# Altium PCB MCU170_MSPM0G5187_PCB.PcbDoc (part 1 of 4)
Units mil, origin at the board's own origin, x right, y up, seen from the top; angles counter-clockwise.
Board outline 2300 x 4450 mil, 4 copper layers (Top Layer, VCC Layer, GND Layer, Bottom Layer), stack 62.4 mil thick; 276 components, 190 nets, 913 pads, 323 vias.
Unrouted connection lines stored in the file: 4.
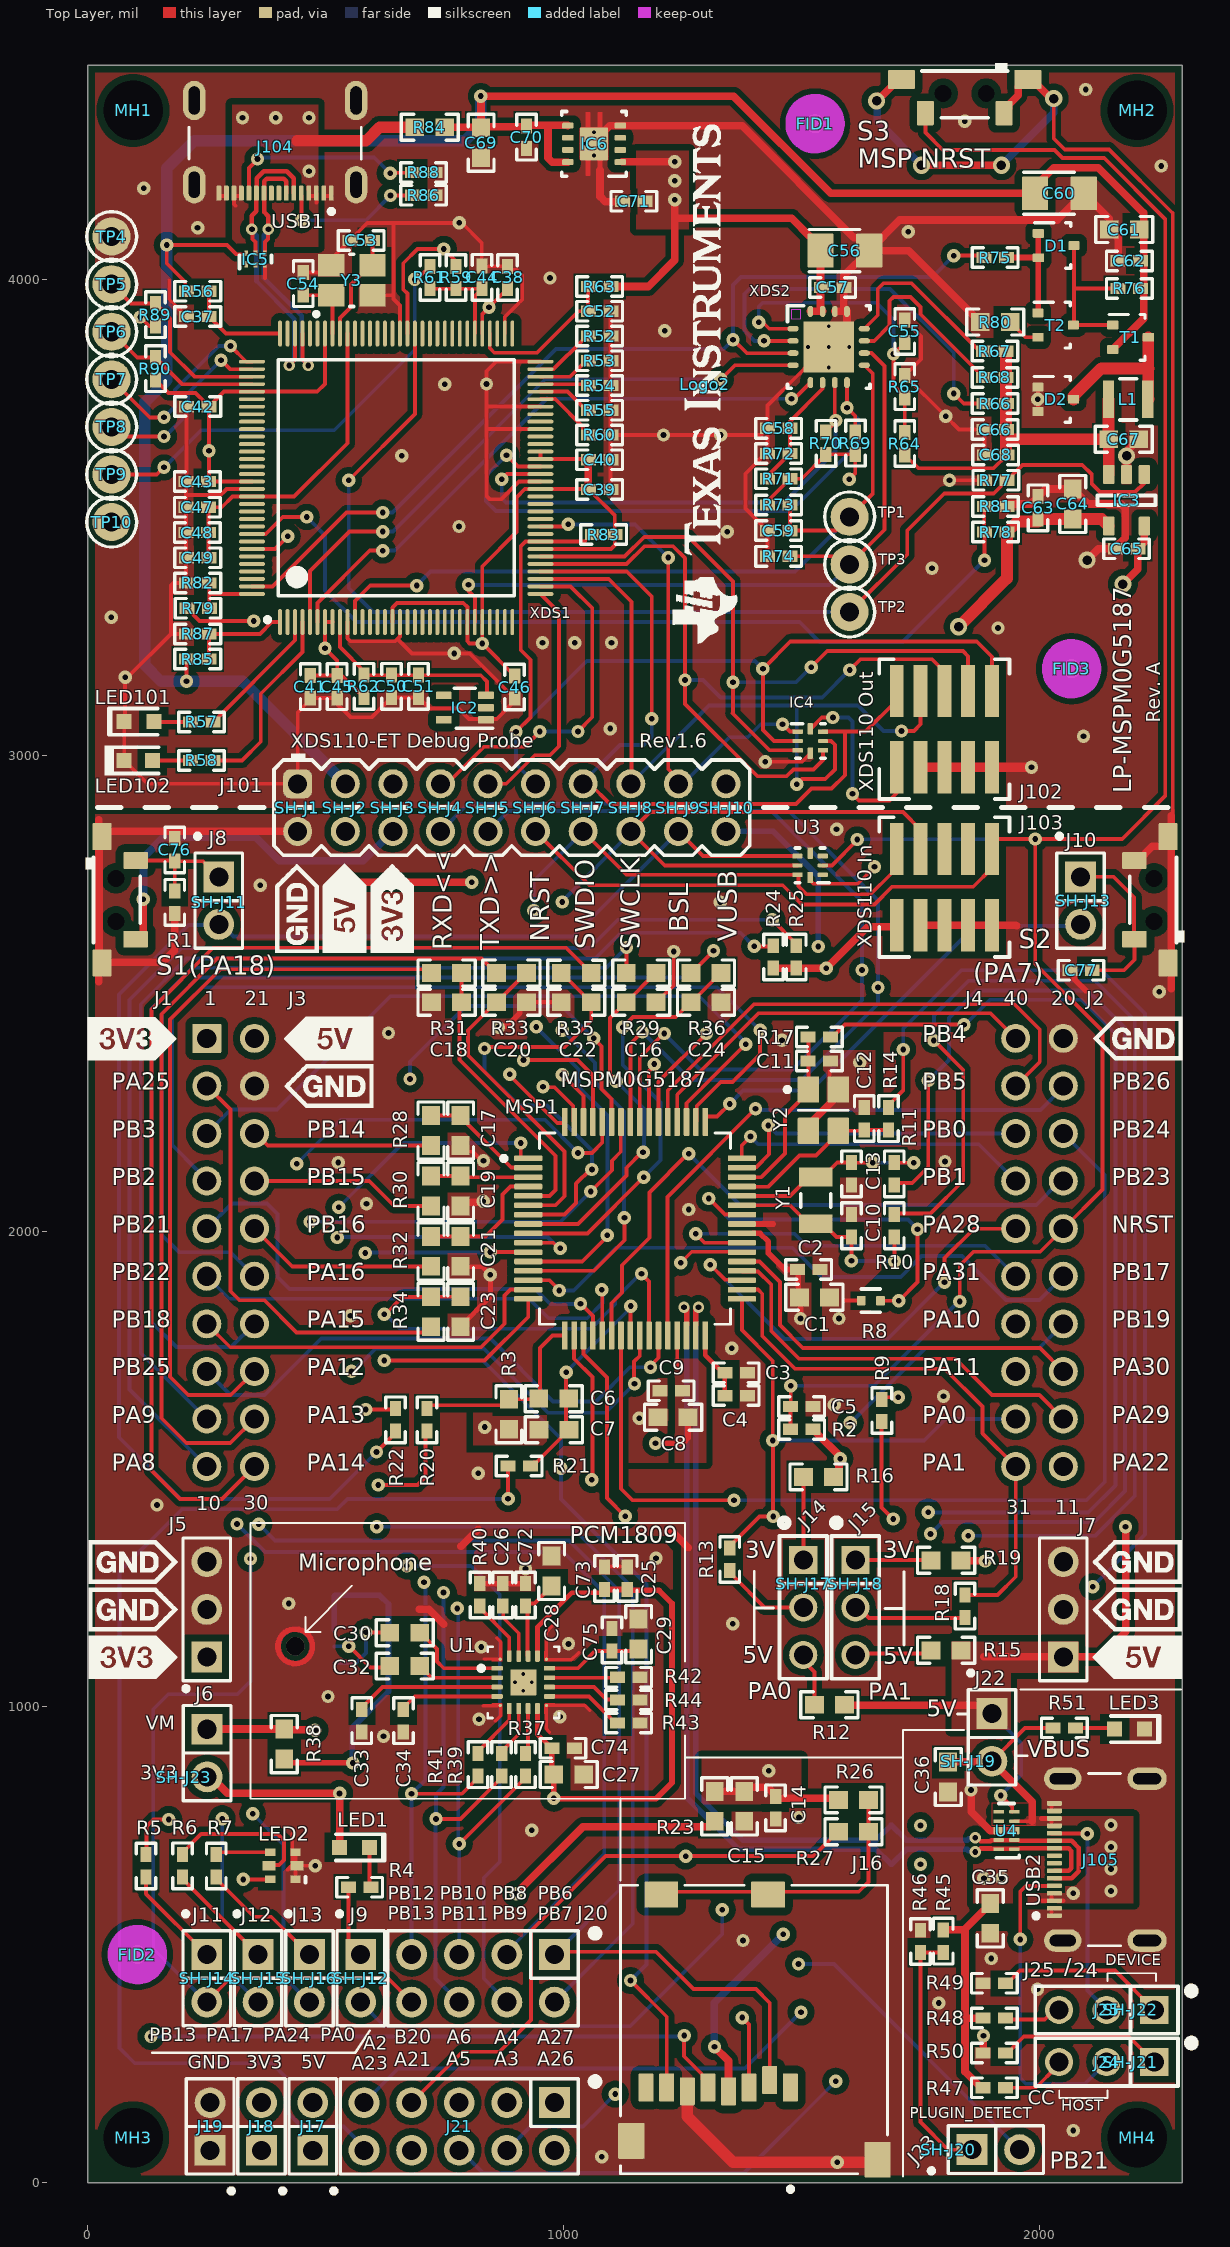
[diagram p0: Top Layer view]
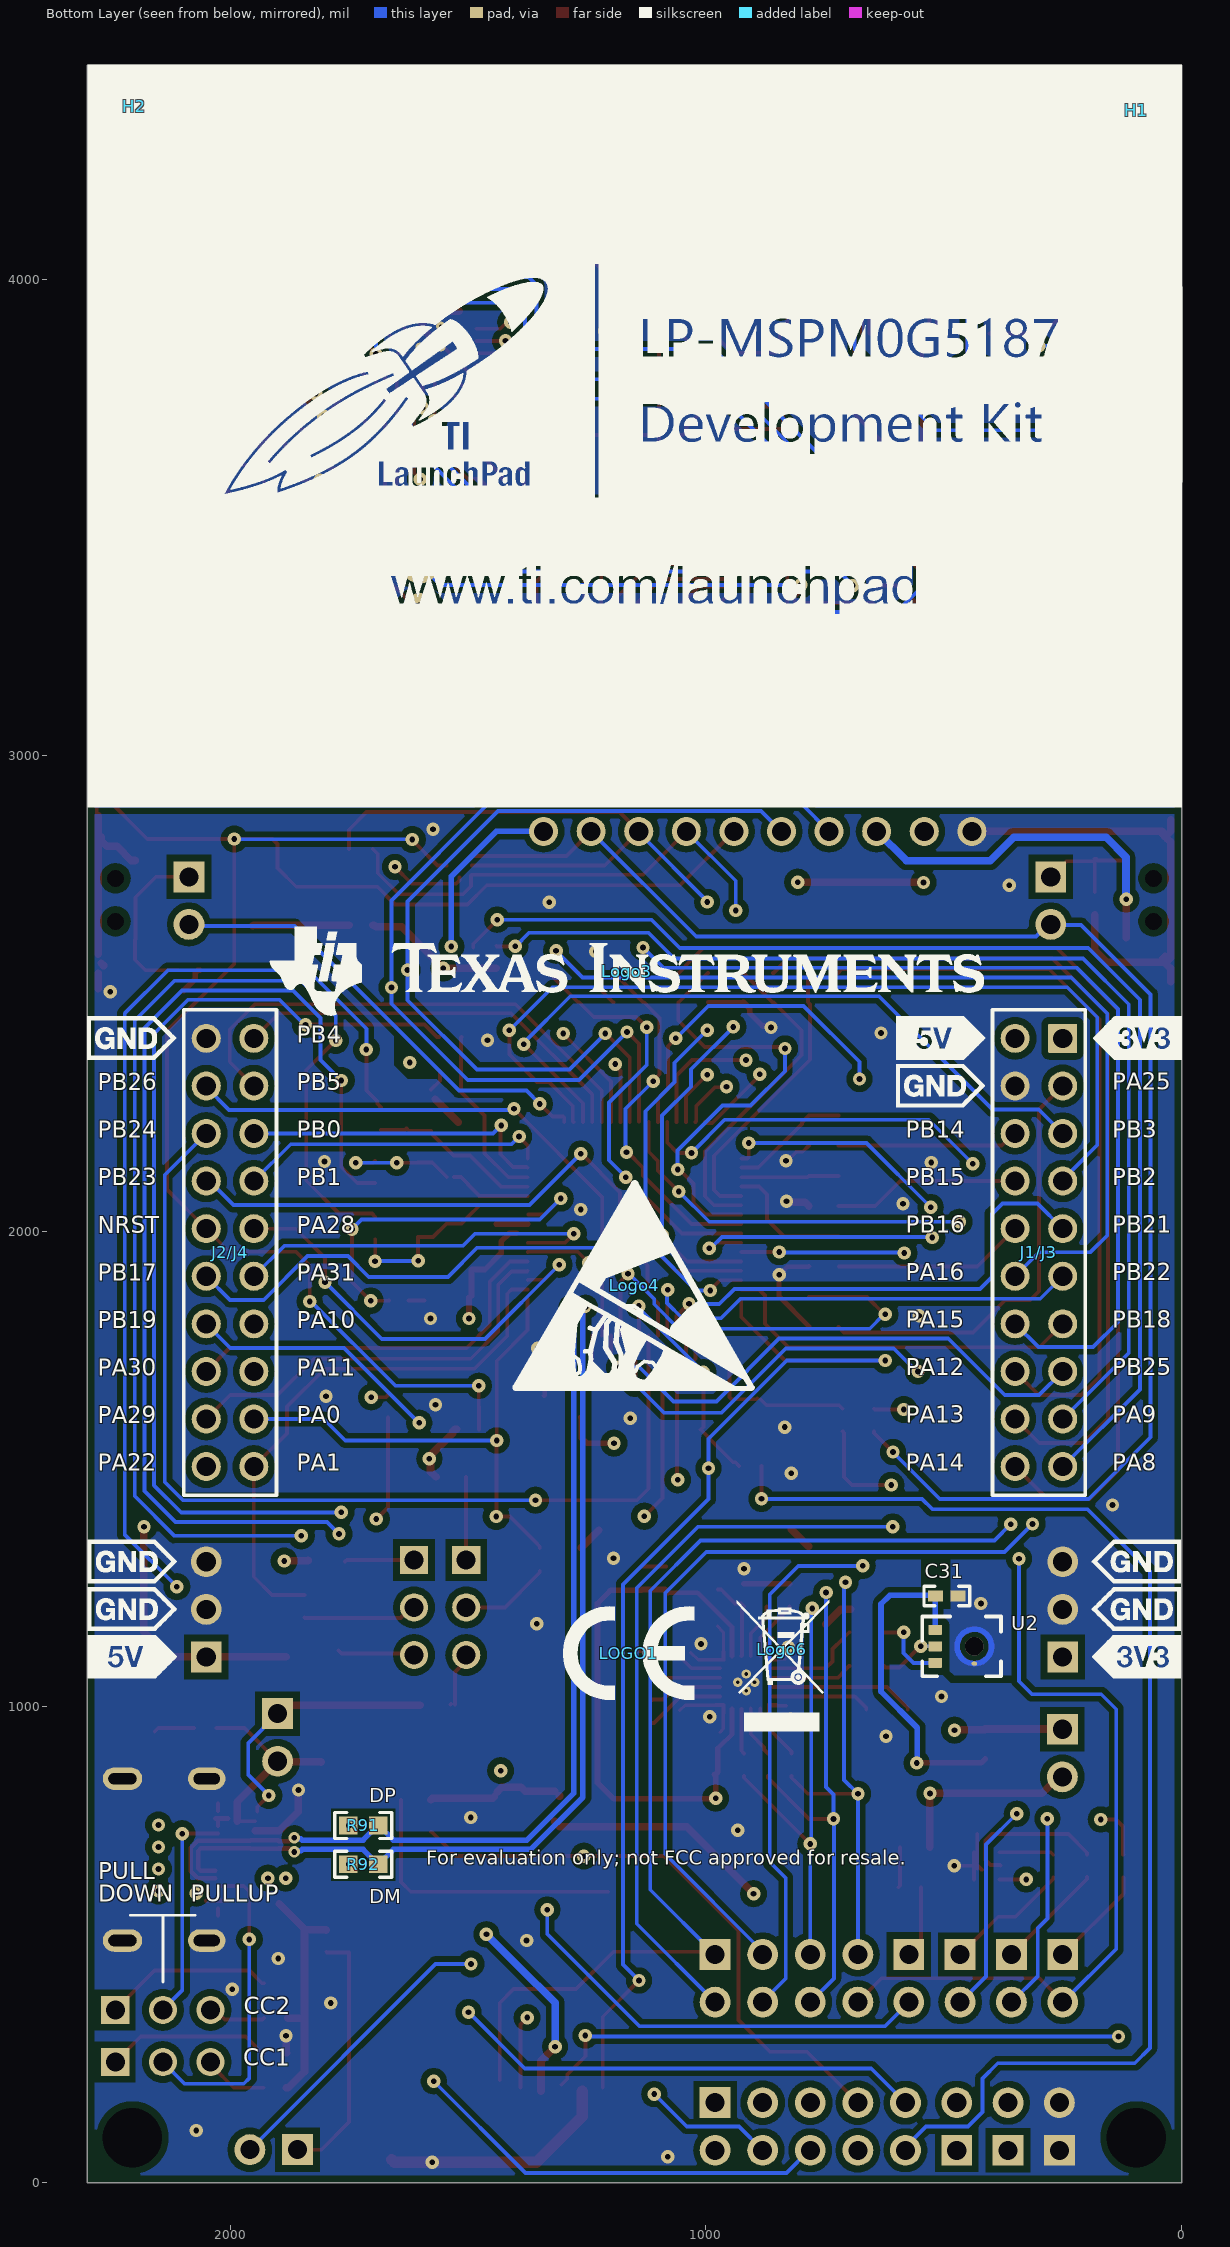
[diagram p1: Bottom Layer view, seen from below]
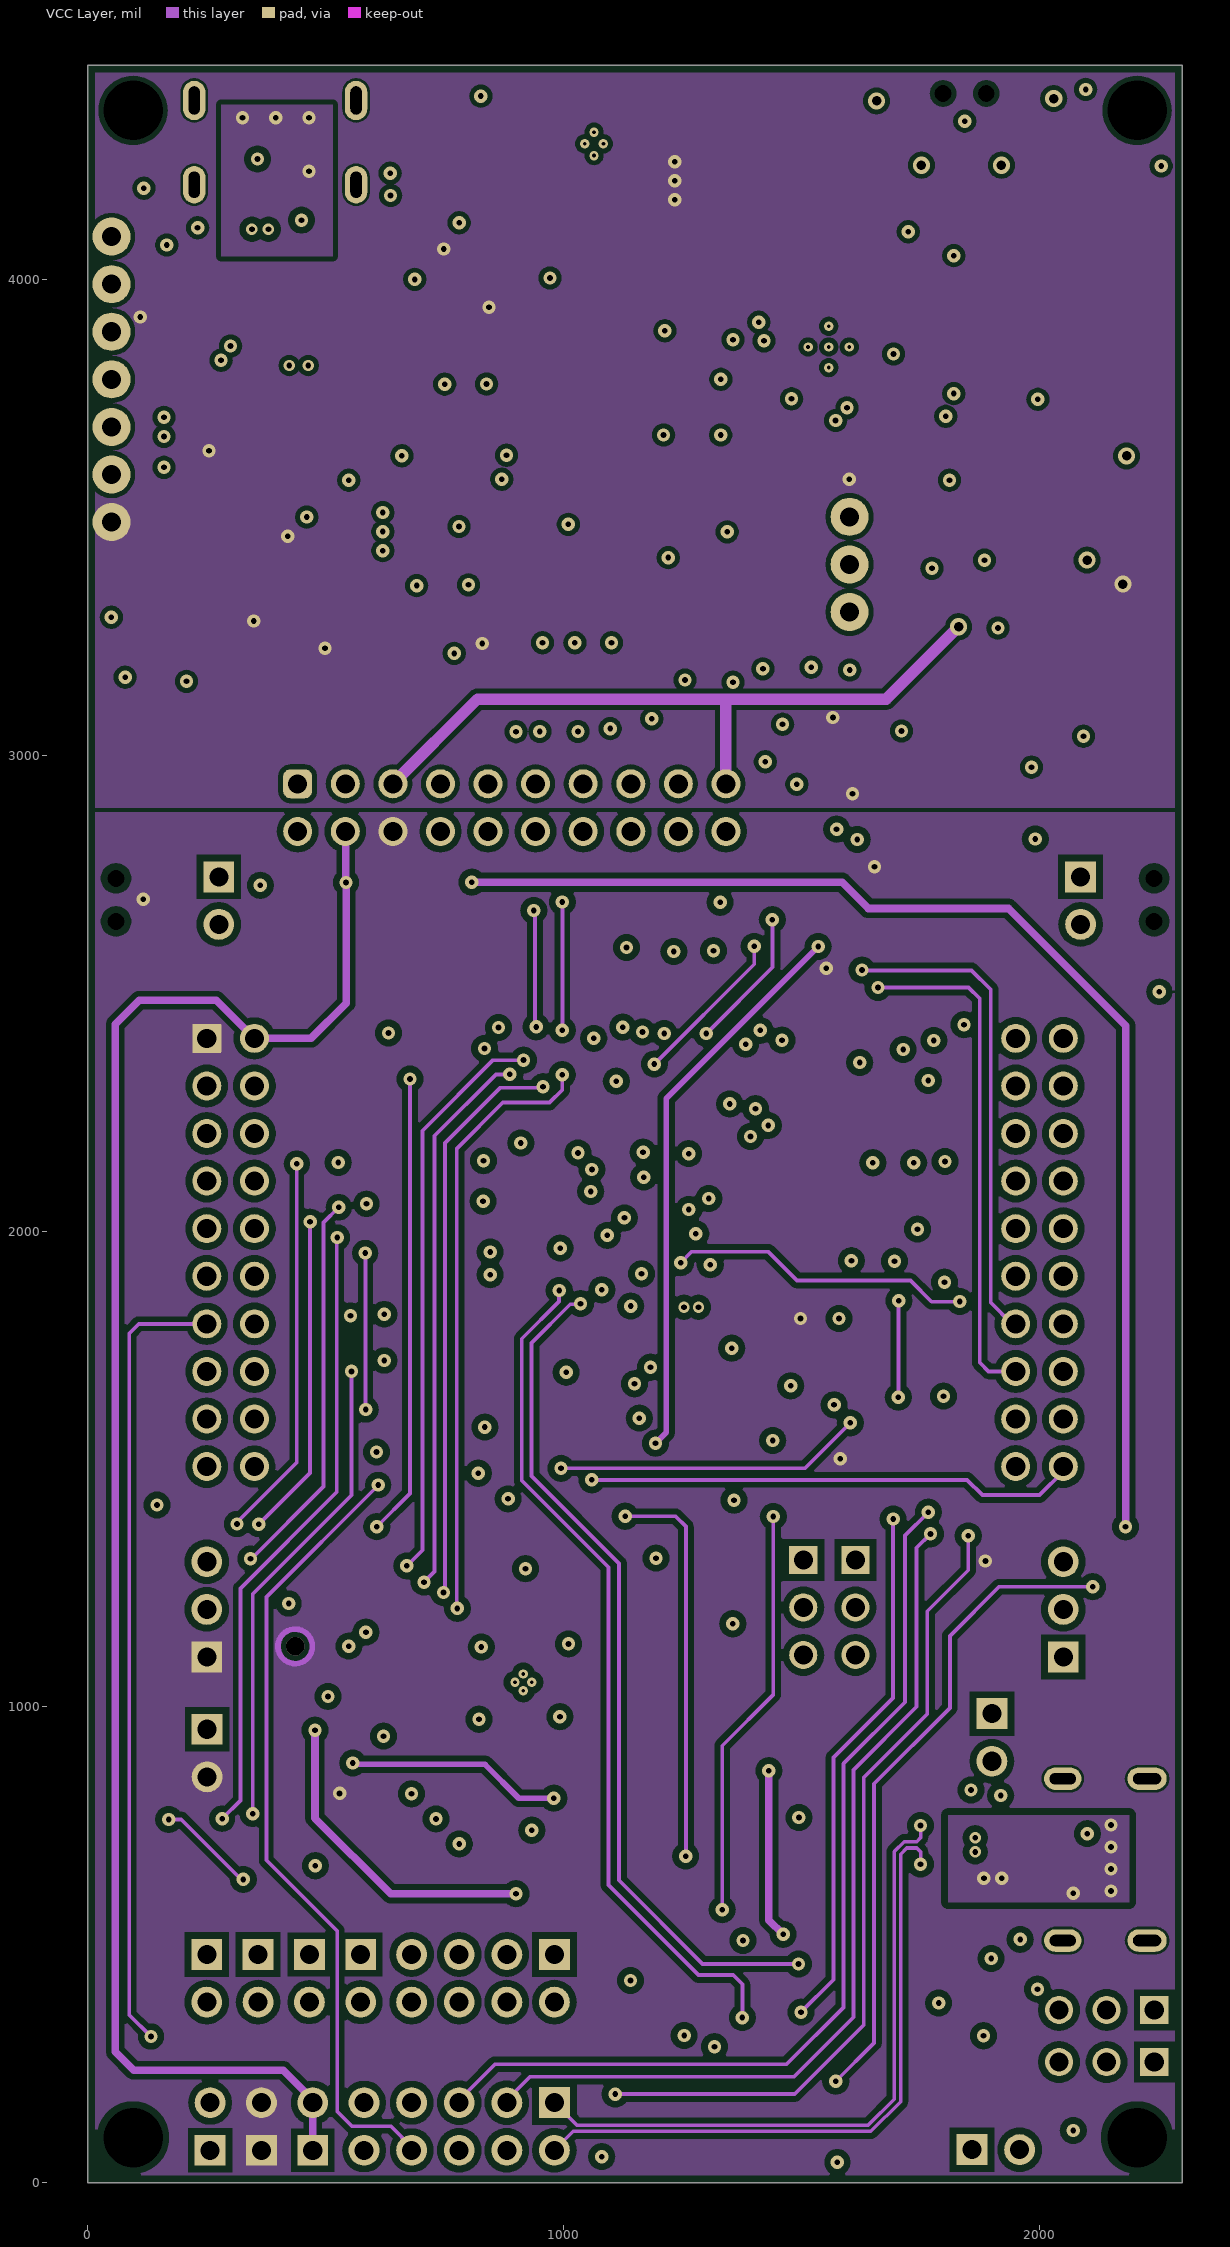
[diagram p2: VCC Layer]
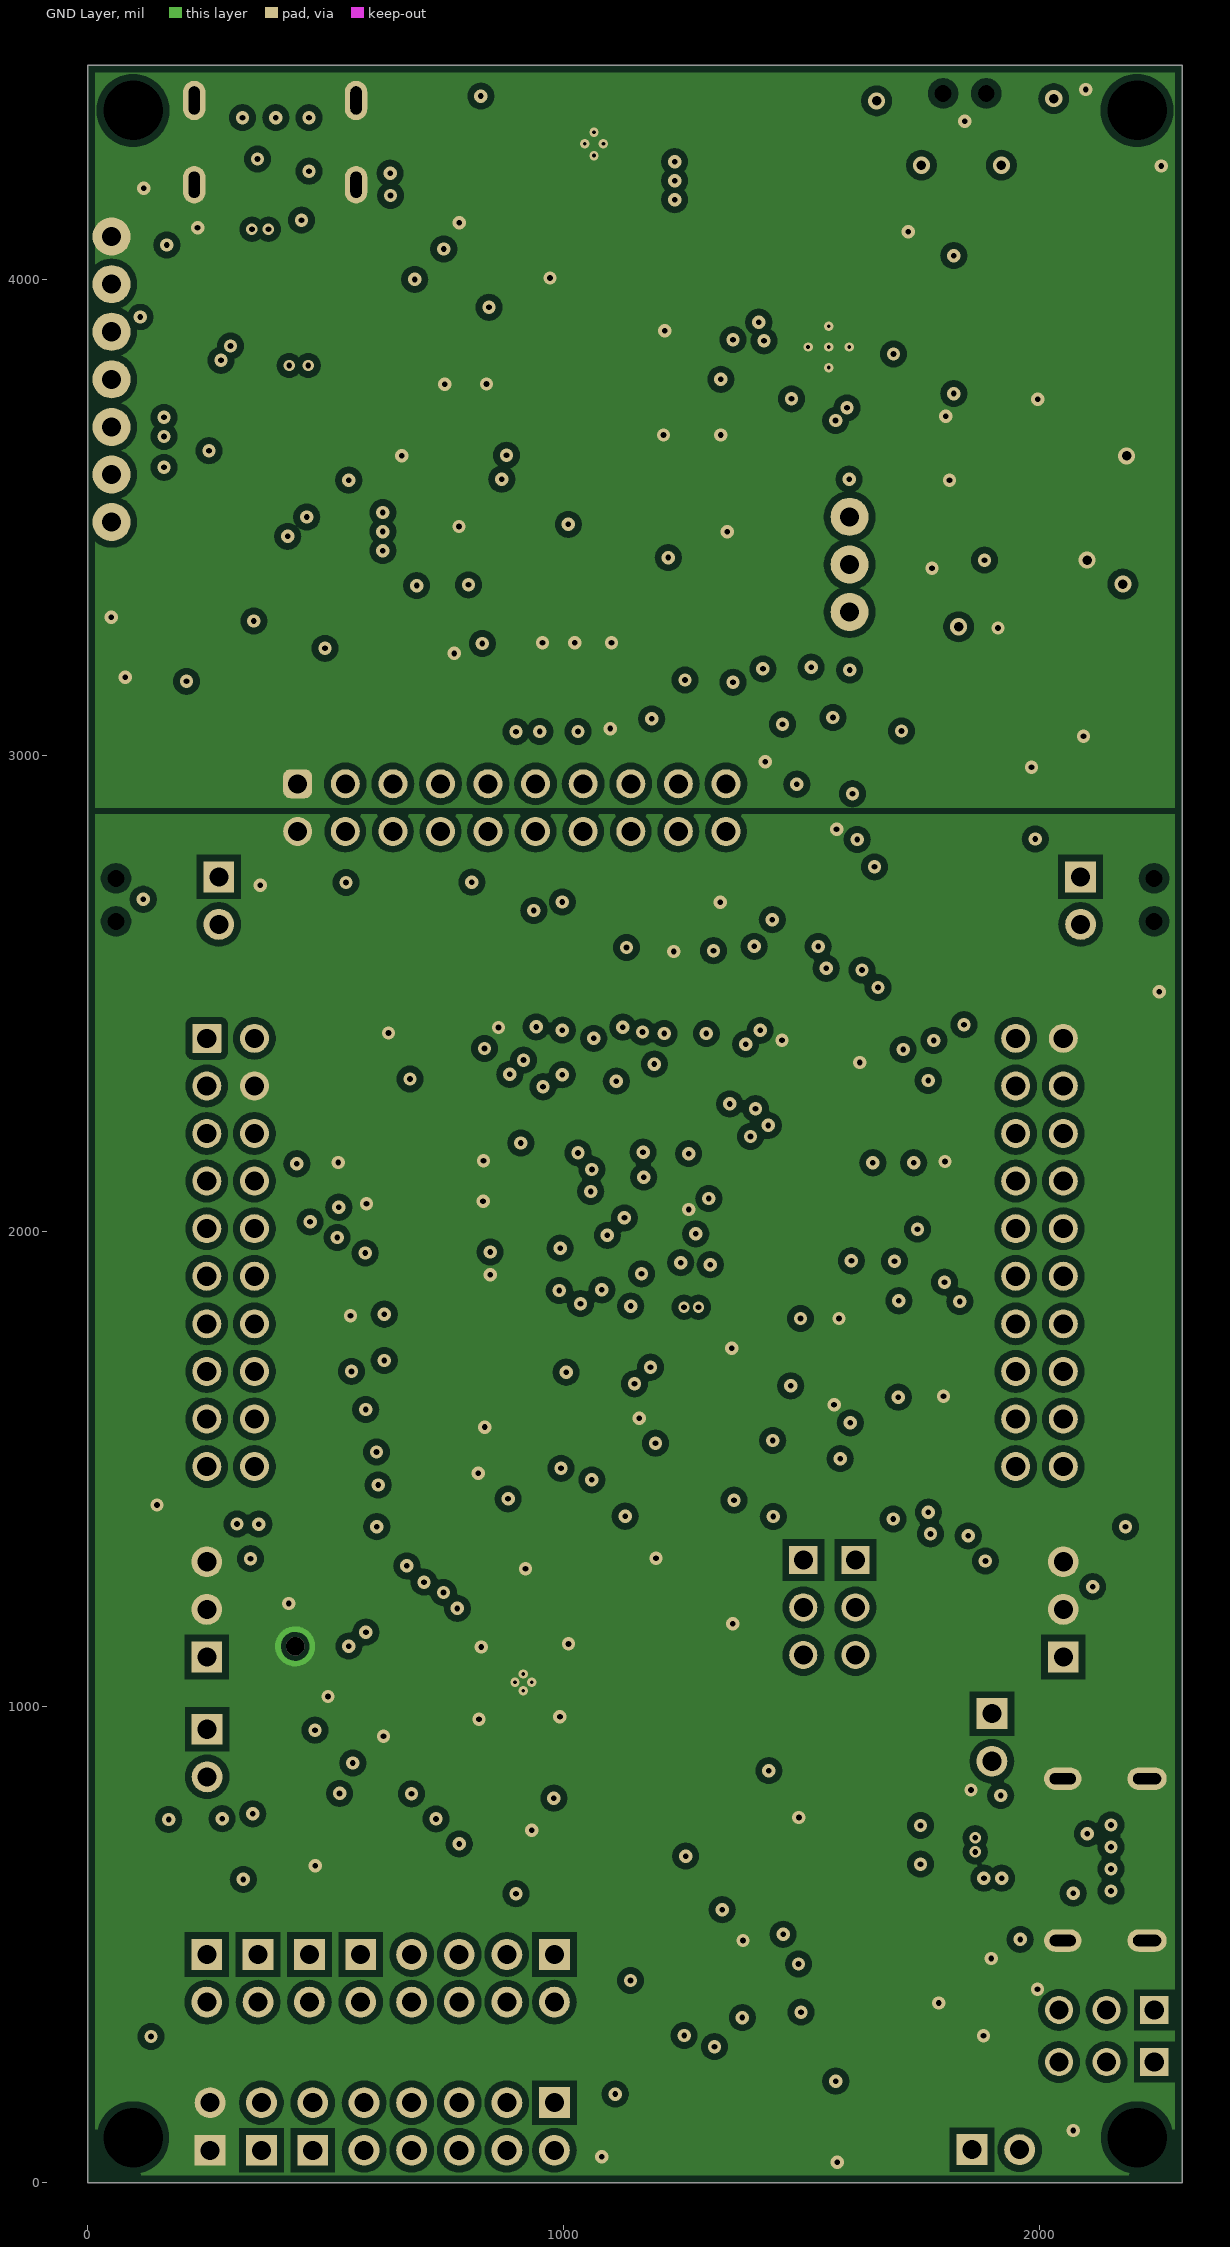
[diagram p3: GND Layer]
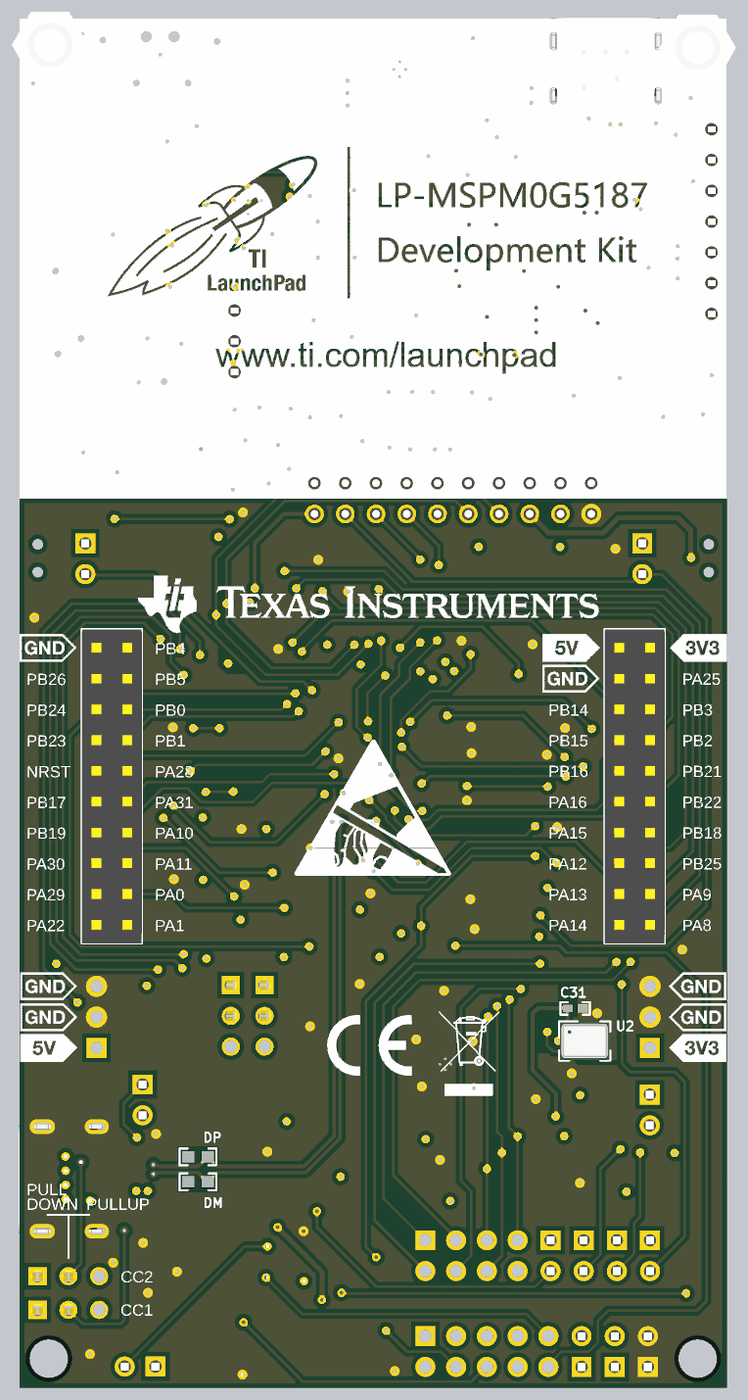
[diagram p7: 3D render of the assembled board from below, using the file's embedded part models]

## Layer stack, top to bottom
Top Solder: solder mask 0.984, SM-004, Dk 4
Top Layer: signal copper 1.4
Dielectric 2: core 8.4, FR-4, Dk 4.2
VCC Layer: signal copper 1.4
Dielectric1: prepreg 40, FR-4, Dk 4.2
GND Layer: signal copper 1.4
Dielectric 3: core 8.4, FR-4, Dk 4.2
Bottom Layer: signal copper 1.4
Bottom Solder: solder mask 0.984, SM-004, Dk 4

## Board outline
0,0 2300,0 2300,4450 0,4450

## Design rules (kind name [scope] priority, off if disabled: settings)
AcuteAngle [All] p1: minimum=4.50000000000000E+0001 checktracksonly=FALSE
AssemblyTestPointUsage [All] p1: valid=2
BoardOutlineClearance BoardOutlineClearance_MountingHoles [OnCopper and InComponentClass('Mounting Holes')] p1: gap=15 ignorepadtopadclearanceinfootprint=FALSE
BoardOutlineClearance BoardOutlineClearance_Poly [OnCopper and IsPoly] p2: gap=15 ignorepadtopadclearanceinfootprint=FALSE
BoardOutlineClearance [OnCopper and Not InComponentClass('Logo') and not InComponentClass('FiducialMark') and not InRegion(1000,500,4000,800) and not InPoly] p3: gap=10 ignorepadtopadclearanceinfootprint=FALSE
Clearance SMD_TYPE_C [((InComponent('J104')) OR (InComponent('J105')))] p1: gap=5 ignorepadtopadclearanceinfootprint=FALSE
Clearance SMD [InNamedPolygon('GND_LAYER_GND_P-001')] p2: gap=10 ignorepadtopadclearanceinfootprint=FALSE except(0: Arc-Hole Track-Hole SMDPad-Hole THPad-Hole Via-Hole Fill-Hole Poly-Hole Region-Hole Text-Hole; 20: SMDPad-SMDPad SMDPad-THPad SMDPad-Via SMDPad-Fill SMDPad-Poly SMDPad-Region SMDPad-Text)
Clearance Clearance_FiducialMark [IsKeepOut and InComponentClass('FiducialMark') vs IsPad and InComponentClass('FiducialMark')] p3: gap=0 ignorepadtopadclearanceinfootprint=FALSE
Clearance Clearance_Keepouts [((IsTrack Or IsArc) And Not InPoly) And IsFree and IsKeepOut vs ((IsTrack Or IsArc) And Not InPoly) And IsFree and IsKeepOut] p4: gap=0 ignorepadtopadclearanceinfootprint=FALSE
Clearance Clearance_Poly [InPolygon] p5: gap=14 ignorepadtopadclearanceinfootprint=FALSE except(0: Arc-Hole Track-Hole SMDPad-Hole THPad-Hole Via-Hole Fill-Hole Poly-Hole Region-Hole Text-Hole; 12: Arc-Fill Arc-Poly Arc-Region Track-Fill Track-Poly Track-Region; 15: THPad-THPad; 16: SMDPad-Fill SMDPad-Poly SMDPad-Region)
Clearance [All] p6: gap=6 ignorepadtopadclearanceinfootprint=FALSE
ComponentClearance ComponentClearance_Standoffs [HasFootprint('KY_MAE-10') vs HasFootprint('NPTH125mil')] p1: gap=0 collisioncheckmode=3 verticalgap=0 showdistances=FALSE
ComponentClearance ComponentClearance_2PinHeaders [HasFootprint('TSW-102-07-G-S') vs HasFootprint('TSW-102-07-G-S')] p2: gap=0 collisioncheckmode=3 verticalgap=0 showdistances=FALSE
ComponentClearance ComponentClearance_TestPoint [HasFootprint('Keystone5001') vs HasFootprint('Keystone5001')] p3: gap=0 collisioncheckmode=3 verticalgap=0 showdistances=FALSE
ComponentClearance ComponentClearance_MountingHoles_FiducialMarks [InComponentClass('Mounting Holes') vs InComponentClass('FiducialMark')] p4: gap=0 collisioncheckmode=3 verticalgap=0 showdistances=FALSE
ComponentClearance ComponentClearance_ShuntToShunt [InComponentClass('Shunt') vs InComponentClass('Shunt')] p5: gap=0 collisioncheckmode=3 verticalgap=0 showdistances=FALSE
ComponentClearance ComponentClearance_Shunt [InComponentClass('Header') vs InComponentClass('Shunt')] p6: gap=0 collisioncheckmode=3 verticalgap=0 showdistances=FALSE
ComponentClearance ComponentClearance_Logo [InComponentClass('Logo')] p7: gap=0 collisioncheckmode=3 verticalgap=0 showdistances=FALSE
ComponentClearance ComponentClearance_ScrewToNut [(HasFootprint('NY PMS 440 0025 PH')) vs (HasFootprint('Keystone_1902C'))] p8: gap=5 collisioncheckmode=3 verticalgap=10 showdistances=FALSE
ComponentClearance ComponentClearance_MountingHoles [InComponentClass('Mounting Holes')] p9: gap=250 collisioncheckmode=3 verticalgap=100000 showdistances=FALSE
ComponentClearance ComponentClearance_SmallPassives [HasFootprint('0201*') or HasFootprint('0402*') or HasFootprint('0508') or HasFootprint('0603*') or HasFootprint('0612') or HasFootprint('0805*') or HasFootprint('0815*') or HasFootprint('0830*') or HasFootprint('1206*') or HasFootprint('1210*') or HasFootprint('1808*') or HasFootprint('1812*') or HasFootprint('1825*') or HasFootprint('2010*') or HasFootprint('2220*') or HasFootprint('2225*') or HasFootprint('2512*') or HasFootprint('2728*') or HasFootprint('3518*') vs HasFootprint('0201*') or HasFootprint('0402*') or HasFootprint('0508') or HasFootprint('0603*') or HasFootprint('0612') or HasFootprint('0805*') or HasFootprint('0815*') or HasFootprint('0830*') or HasFootprint('1206*') or HasFootprint('1210*') or HasFootprint('1808*') or HasFootprint('1812*') or HasFootprint('1825*') or HasFootprint('2010*') or HasFootprint('2220*') or HasFootprint('2225*') or HasFootprint('2512*') or HasFootprint('2728*') or HasFootprint('3518*')] p10: gap=0 collisioncheckmode=3 verticalgap=0 showdistances=FALSE
ComponentClearance ComponentClearance_THtoSMT [IsThruComponent vs IsSMTComponent] p11: gap=0 collisioncheckmode=3 verticalgap=0 showdistances=FALSE
ComponentClearance ComponentClearance_THtoTH [IsThruComponent vs IsThruComponent] p12: gap=0 collisioncheckmode=3 verticalgap=0 showdistances=FALSE
ComponentClearance [All] p13: gap=0 collisioncheckmode=3 verticalgap=0 showdistances=FALSE
DiffPairsRouting DiffPair_MSPDiffPairsRouting [InDifferentialPair ('DifferentialPair_MSP')] p1: maxlimit=16 minlimit=4 mostfreqgap=8 toplayer_prefgap=6 toplayer_minwidth=6 toplayer_maxwidth=12 toplayer_prefwidth=12 midlayer1_prefgap=6 midlayer1_minwidth=6 midlayer1_maxwidth=8 midlayer1_prefwidth=8 midlayer2_prefgap=6 midlayer2_minwidth=6 midlayer2_maxwidth=8 midlayer2_prefwidth=8 bottomlayer_minwidth=6 bottomlayer_maxwidth=12 bottomlayer_prefwidth=12 maxuncoupledlength=100
DiffPairsRouting DiffPair_XDS_USBDiffPairsRouting [InDifferentialPairClass('XDS_USB')] p2: maxlimit=10 minlimit=6 mostfreqgap=8 toplayer_minwidth=6 toplayer_maxwidth=10 toplayer_prefwidth=8 midlayer1_minwidth=6 midlayer1_maxwidth=10 midlayer1_prefwidth=8 midlayer2_minwidth=6 midlayer2_maxwidth=10 midlayer2_prefwidth=8 bottomlayer_minwidth=6 bottomlayer_maxwidth=10 bottomlayer_prefwidth=8 maxuncoupledlength=500
DiffPairsRouting [All] p3: maxlimit=100 minlimit=6 mostfreqgap=10 toplayer_minwidth=6 toplayer_maxwidth=16 toplayer_prefwidth=10 midlayer1_minwidth=6 midlayer1_maxwidth=16 midlayer1_prefwidth=10 midlayer2_minwidth=6 midlayer2_maxwidth=16 midlayer2_prefwidth=10 bottomlayer_minwidth=6 bottomlayer_maxwidth=16 bottomlayer_prefwidth=10 maxuncoupledlength=1000
FabricationTestPointUsage TestPointUsage [All] p1: valid=2 allowmultiple=FALSE
FabricationTestpoint Testpoint [All] p1: side=3 testpointundercomponent=TRUE minsize=40 maxsize=100 preferedsize=60 minholesize=0 maxholesize=40 preferedholesize=32 testpointgrid=1 allowsidetop=TRUE allowsidebottom=TRUE usegrid=TRUE gridtolerance=0.01
FanoutControl Fanout_LCC [IsLCC] p1: bgadir=Out bgaviamode=Centered fanoutstyle=Auto fanoutdirection=Alternating viagrid=1 // Fanout_LCC (Default Rule)
FanoutControl Fanout_BGA [IsBGA] p2: bgadir=Out bgaviamode=Centered fanoutstyle=Auto fanoutdirection=Alternating viagrid=1 // Fanout_BGA (Default Rule)
FanoutControl Fanout_Default [All] p4: bgadir=Out bgaviamode=Centered fanoutstyle=Auto fanoutdirection=Alternating viagrid=1 // Fanout_Default (Default Rule)
FanoutControl Fanout_Small [(CompPinCount < 5)] p5: bgadir=Out bgaviamode=Centered fanoutstyle=Auto fanoutdirection=OutThenIn viagrid=1 // Fanout_Small (Default Rule)
HoleSize [All] p1: absolutevalues=TRUE maxlimit=251 minlimit=7.87 maxpercent=80.000 minpercent=20.000
MatchedLengths DiffPair_MSPMatchedLengths [InDifferentialPair ('DifferentialPair_MSP')] p1: tolerance=2 checknetsindiffpair=FALSE checkdiffpairvsdiffpair=TRUE checkxsignals=TRUE checkothers=TRUE
MatchedLengths DiffPair_XDS_USBMatchedLengths [InDifferentialPairClass('XDS_USB')] p2: tolerance=2 checknetsindiffpair=FALSE checkdiffpairvsdiffpair=TRUE checkxsignals=TRUE checkothers=TRUE
MinimumAnnularRing MinimumAnnularRing_ThermalPadVias [IsVia and InAnyComponent] p1: minimumring=5.91
MinimumAnnularRing [All] p2: minimumring=6
MinimumSolderMaskSliver MinimumSolderMaskSliver_XDS [HasFootprint('PDT0128A')] p1: minsoldermaskwidth=3.6
MinimumSolderMaskSliver MinimumSolderMaskSliver_Logo [InComponentClass('Logo') vs InComponentClass('Logo')] p2: minsoldermaskwidth=0.7
MinimumSolderMaskSliver [All] p3: minsoldermaskwidth=3.94
PlaneClearance [All] p1: clearance=10
PlaneConnect [All] p1: planeconnectstyle=Relief reliefexpansion=10 reliefentries=4 reliefconductorwidth=10 reliefairgap=10
PolygonConnect XDS_USB_VCC_Polygon [All vs IsNamedPolygon('TOP_LAYER_XDS_VBUS_P044')] p1: connectstyle=Direct reliefconductorwidth=10 reliefentries=4 polygonreliefangle="90 Angle" airgapwidth=10
PolygonConnect PolygonConnect_General [All] p2: connectstyle=Direct reliefconductorwidth=10 reliefentries=4 polygonreliefangle="90 Angle" airgapwidth=10
RoutingVias ThermalPadVias [IsVia and InAnyComponent] p1: holewidth=7.87 width=19.68 viastyle="Through Hole" minholewidth=7.87 minwidth=19.68 maxholewidth=16 maxwidth=30
RoutingVias [All] p2: holewidth=12 width=28 viastyle="Through Hole" minholewidth=7.87 minwidth=26 maxholewidth=40 maxwidth=65
SilkToBoardRegionClearance [Not ((IsComment or IsDesignator) And (Hide <> 'False')) and not InRegion(1000,500,4000,800)] p1:
SilkToSilkClearance SilkToSilkClearance_Pb-FreeLogo [(HasFootprint('Pb-Free_Overlay_Medium') OR HasFootprint('Pb-Free_Overlay_Small')) vs (HasFootprint('Pb-Free_Overlay_Medium') OR HasFootprint('Pb-Free_Overlay_Small'))] p1: silktosilkclearance=0
SilkToSilkClearance [All] p2: silktosilkclearance=0
SilkToSolderMaskClearance SilkToComponentPadClearance [(IsPad or IsFill or IsRegion) and InAnycomponent] p1: minsilkscreentomaskgap=0 clearancetoexposedcopper=TRUE
SilkToSolderMaskClearance "Silk to Solder Mask Opening" [All] p2: minsilkscreentomaskgap=0 clearancetoexposedcopper=FALSE
SolderMaskExpansion SolderMaskExpansion_via [isvia] p1: expansion=-16 istentingtop=FALSE
SolderMaskExpansion [All] p2: expansion=2 istentingtop=FALSE
Width Width_Signal_16mil [InNetClass('Power_16mil')] p1: maxlimit=24 minlimit=8 preferedwidth=16 minimp=50.000000 maximp=50.000000 favimp=50.000000
Width Width_Signal_8mil [InNetClass('SIgnal_8mil')] p2: maxlimit=16 minlimit=8 preferedwidth=8 minimp=50.000000 maximp=50.000000 favimp=50.000000
Width [All] p3: maxlimit=100 minlimit=6 preferedwidth=10 checkconnectedcopper=TRUE
14 further rules are at their usual default settings.

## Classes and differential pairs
differential pair class Header_USB: Header_USB
differential pair class MSP_USB: DifferentialPair_MSP
differential pair class XDS_USB: DifferentialPair_XDS
component class MCU170_03_MSPM0G5187_Target_Interface: C25 C26 C27 C28 C29 C30 C31 C32 C33 C34 C35 C36 C72 C73 C74 C75 J22 J23 J24 J25 J105 LED3 R37 R38 R39 R40 R41 R42 R43 R44 R45 R46 R47 R48 R49 R50 R51 U1 U2 U4
component class MCU170_08_Hardware: "30N.C. ROUTE" !PCB FID1 FID2 FID3 H1 H2 LOGO1 Logo2 Logo3 Logo4 Logo5 Logo6 MH1 MH2 MH3 MH4 SH-J1 SH-J2 SH-J3 SH-J4 SH-J5 SH-J6 SH-J7 SH-J8 SH-J9 SH-J10 SH-J11 SH-J12 SH-J13 SH-J14 SH-J15 SH-J16 SH-J17 SH-J18 SH-J19 SH-J20 SH-J21 SH-J22 SH-J23 SH-J101A SH-J101B SH-J101C SH-J101D SH-J101E SH-J101F SH-J101G SH-J101H SH-J101I SH-J101J ZZ1 ZZ2 ZZ3 ZZ4
component class MCU170_07_XDS110-ET_USB_Power: "30N.C. ROUTE" C69 C70 C71 IC5 IC6 J104 R84 R85 R86 R87 R88 R89 R90 TP4 TP5 TP6 TP7 TP8 TP9 TP10
component class MCU170_06_XDS110_Target_Interface: "30N.C. ROUTE" IC4 J101 J102 J103 R83 U3
component class MCU170_05_XDS110-ET_EnergyTrace: "30N.C. ROUTE" C55 C56 C57 C58 C59 C60 C61 C62 C63 C64 C65 C66 C67 C68 D1 D2 IC3 L1 R64 R65 R66 R67 R68 R69 R70 R71 R72 R73 R74 R75 R76 R77 R78 R79 R80 R81 R82 T1 T2 XDS2
component class MCU170_04_XDS110_Debug_Probe: "30N.C. ROUTE" C37 C38 C39 C40 C41 C42 C43 C44 C45 C46 C47 C48 C49 C50 C51 C52 C53 C54 IC2 LED101 LED102 R52 R53 R54 R55 R56 R57 R58 R59 R60 R61 R62 R63 TP1 TP2 TP3 XDS1 Y3
component class MCU170_02_BoosterPack_Connectors: "30N.C. ROUTE" C14 C15 C16 C17 C18 C19 C20 C21 C22 C23 C24 J1/J3 J2/J4 J16 J17 J18 J19 J20 J21 R23 R24 R25 R26 R27 R28 R29 R30 R31 R32 R33 R34 R35 R36 R91 R92
component class MCU170_01_MSPM0G5187_Target_Device: "30N.C. ROUTE" C1 C2 C3 C4 C5 C6 C7 C8 C9 C10 C11 C12 C13 C76 C77 J5 J6 J7 J8 J9 J10 J11 J12 J13 J14 J15 LED1 LED2 MSP1 R1 R2 R3 R4 R5 R6 R7 R8 R9 R10 R11 R12 R13 R14 R15 R16 R17 R18 R19 R20 R21 R22 S1 S2 S3 Y1 Y2
component class FiducialMark: "30N.C. ROUTE" FID1 FID2 FID3
component class AssemblyNote: "30N.C. ROUTE" ZZ2 ZZ3 ZZ4 ZZ6
component class Logo: "30N.C. ROUTE" Logo2 Logo3
component class Header: J5 J6 J7 J8 J9 J10 J11 J12 J13 J14 J15 J17 J18 J19 J20 J21 J22 J23 J24 J25 J101
component class Shunt: SH-J1 SH-J2 SH-J3 SH-J4 SH-J5 SH-J6 SH-J7 SH-J8 SH-J9 SH-J10 SH-J11 SH-J12 SH-J13 SH-J14 SH-J15 SH-J16 SH-J17 SH-J18 SH-J19 SH-J20 SH-J21 SH-J22 SH-J23
differential pair Header_USB: +NetJ21_1 -NetJ21_2
differential pair DifferentialPair_MSP: +31_PA27_DP -30_PA26_DM
differential pair DifferentialPair_XDS: +XDS_DP -XDS_DM

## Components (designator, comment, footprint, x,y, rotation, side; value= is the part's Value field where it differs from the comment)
C1 "GRM188R60J106ME84" 0603 1526.99,1860.62 r0 top value=10uF
C2 "GRM155R61H104ME14D" 0402 1515.01,1919.19 r0 top value=0.1uF
C3 "GRM155R60J474KE19D" 0402 1362.36,1702.11 r0 top value=0.47uF
C4 "GRM155R61H104ME14D" 0402 1362.36,1654.1 r0 top value=0.1uF
C5 "GRM155R61C103KA01D" 0402 1500.28,1631.29 r0 top value=0.01uF
C6 "C1608X5R1E105K080AC" 0603 979.1,1647.87 r180 top value=1uF
C7 "C1608X5R1E105K080AC" 0603 979.57,1582.37 r180 top value=1uF
C8 "C1608X5R1E105K080AC" 0603 1230,1608.79 r0 top value=1uF
C9 "GRM155R61H104ME14D" 0402 1226,1664.49 r0 top value=0.1uF
C10 "GRM1555C1H150JA01D" 0402 1605,2011.17 r90 top value=15pF
C11 "GRM1555C1H150JA01D" 0402 1537.36,2357.28 r0 top value=15pF
C12 "GRM1555C1H150JA01D" 0402 1631.61,2236.41 r90 top value=15pF
C13 "GRM1555C1H150JA01D" 0402 1605,2120.31 r270 top value=15pF
C14 "C0402C104K8RACTU" 0402 1445.52,787.84 r90 top value=0.1uF
C15 "EMK107BBJ106MA-T" 0603 1379.42,790.91 r90 top value=10uF
C16 "GCM188R71C104KA37J" 0603 1162.81,2480.8 r180 top value=0.1uF
C17 "GCM188R71C104KA37J" 0603 783.43,2211.25 r90 top value=0.1uF
C18 "GCM188R71C104KA37J" 0603 753.88,2480.87 r0 top value=0.1uF
C19 "GCM188R71C104KA37J" 0603 783.43,2084.27 r90 top value=0.1uF
C20 "GCM188R71C104KA37J" 0603 890.19,2480.87 r180 top value=0.1uF
C21 "GCM188R71C104KA37J" 0603 783.43,1957.3 r90 top value=0.1uF
C22 "GCM188R71C104KA37J" 0603 1026.5,2480.87 r0 top value=0.1uF
C23 "GCM188R71C104KA37J" 0603 783.43,1830.32 r90 top value=0.1uF
C24 "GCM188R71C104KA37J" 0603 1299.12,2480.87 r180 top value=0.1uF
C25 "GRM155R61A105KE15D" 0402 1133.72,1270 r90 top value=1uF
C26 "GRM155R61A105KE15D" 0402 871.91,1235.28 r270 top value=1uF
C27 "C1608X6S1A106M080AC" 0603 1010.7,857.89 r0 top value=10uF
C28 "C1608X6S1A106M080AC" 0603 974.63,1285.63 r270 top value=10uF
C29 "C1608X6S1A106M080AC" 0603 1157.41,1153.04 r270 top value=10uF
C30 "C1608X7R1C105K080AC" 0603 666.16,1156 r180 top value=1uF
C31 "GRM155R61H104ME14D" 0402 493.48,1232.96 r180 bottom value=0.1uF
C32 "C1608X7R1C105K080AC" 0603 666.16,1085.86 r180 top value=1uF
C33 "GRM155R61A105KE15D" 0402 575.73,970.89 r270 top value=1uF
C34 "GRM155R61A105KE15D" 0402 663.11,970.89 r270 top value=1uF
C35 "GRM188R60J106ME84" 0603 1896.49,555.52 r270 top value=10uF
C36 "EMK107BBJ106MA-T" 0603 1807.96,852.71 r270 top value=10uF
C37 "GRM155R70J104KA01D" 0402 231,3922 r180 top value=0.1uF
C38 "GRM155R71E103KA01D" 0402 882,4004 r90 top value=0.01uF
C39 "GRM155R71E103KA01D" 0402 1075.66,3558.44 r0 top value=0.01uF
C40 "GRM155R71E103KA01D" 0402 1075.66,3621 r0 top value=0.01uF
C41 "GRM155R70J104KA01D" 0402 467.5,3144 r270 top value=0.1uF
C42 "GRM155R70J104KA01D" 0402 231,3732.61 r180 top value=0.1uF
C43 "C1005X5R1E105K050BC" 0402 230,3575 r180 top value=1uF
C44 "GRM155R70J104KA01D" 0402 828.45,4004.33 r90 top value=0.1uF
C45 "C1005X5R1E105K050BC" 0402 524,3144 r270 top value=1uF
C46 "GRM155R71E103KA01D" 0402 897,3143.38 r270 top value=0.01uF
C47 "GRM155R60J225KE95D" 0402 230,3521 r180 top value=2.2uF
C48 "GRM155R70J104KA01D" 0402 230,3468 r180 top value=0.1uF
C49 "C1005X5R1E105K050BC" 0402 231,3415 r180 top value=1uF
C50 "GRM155R71E103KA01D" 0402 638,3144.63 r270 top value=0.01uF
C51 "GRM155R70J104KA01D" 0402 695,3144.63 r270 top value=0.1uF
C52 "GRM155R70J104KA01D" 0402 1075.66,3933 r0 top value=0.1uF
C53 "GRM1555C1H120JA01D" 0402 574.38,4081.97 r180 top value=12pF
C54 "GRM1555C1H120JA01D" 0402 452.72,3991 r90 top value=12pF
C55 "GRM1555C1H330JA01D" 0402 1717,3890.62 r90 top value=33pF
C56 "TAJA475K016RNJ" 3216-18 1591.02,4060.58 r0 top value=4.7uF
C57 "GRM155R70J104KA01D" 0402 1565.38,3983 r0 top value=0.1uF
C58 "GRM1555C1H330JA01D" 0402 1452,3687 r180 top value=33pF
C59 "GCM155R71H102KA37D" 0402 1452,3472 r180 top value=1000pF
C60 "TAJA475K016RNJ" 3216-18 2042,4181 r0 top value=4.7uF
C61 "GRM188R61C475KAAJ" 0603 2178,4104.87 r0 top value=4.7uF
C62 "GRM155R70J104KA01D" 0402 2189,4039 r180 top value=0.1uF
C63 "GRM155R70J104KA01D" 0402 1997,3520 r90 top value=0.1uF
C64 "GRM188R60J476ME15D" 0603 2070,3528 r90 top value=47uF
C65 "GRM155R71C224KA12D" 0402 2183,3434 r180 top value=0.22uF
C66 "GRM155R71C224KA12D" 0402 1907,3684.35 r180 top value=0.22uF
C67 "GRM188R61C475KAAJ" 0603 2177,3664 r180 top value=4.7uF
C68 "GRM155R70J104KA01D" 0402 1908,3631 r180 top value=0.1uF
C69 "GRM188R60J106ME84" 0603 826.42,4287.12 r270 top value=10uF
C70 "C1005X5R1E105K050BC" 0402 921.91,4299.1 r270 top value=1uF
C71 "GRM155R60J225KE95D" 0402 1147.66,4164.08 r180 top value=2.2uF
C72 "GRM155R61H104ME14D" 0402 919.92,1235.28 r90 top value=0.1uF
C73 "GRM155R61H104ME14D" 0402 1085.71,1270 r90 top value=0.1uF
C74 "GRM155R61H104ME14D" 0402 998.72,913.16 r0 top value=0.1uF
C75 "GRM155R61H104ME14D" 0402 1101.75,1141.06 r90 top value=0.1uF
C76 "CC0402MRX5R6BB105" 0402 182.65,2800.88 r90 top value=1uF
C77 "CC0402MRX5R6BB105" 0402 2087.24,2548.2 r180 top value=1uF
D1 "BAS40-05W,115" SOT-323 2035,4071.13 r0 top value=40V
D2 "BAS40-05W,115" SOT-323 2034,3748 r0 top value=40V
FID1 "Fiducial" Fiducial10-30 1528.31,4327.4 r0 top
FID2 "Fiducial" Fiducial10-30 104,479.62 r90 top
FID3 "Fiducial" Fiducial10-30 2067.55,3181.73 r90 top
H1 "MAE-10" KY_MAE-10 95,4355 r180 bottom
H2 "MAE-10" KY_MAE-10 2201,4363.78 r180 bottom
IC2 "LM4040C25IDCKR" DCK0005A_N 792.34,3100.16 r180 top
IC3 "TPS2102DBVR" DBV0005A_N 2183,3535.87 r270 top
IC4 "TPD6E004RSER" RSE0008A 1518.56,3029.88 r0 top
IC5 "TPD4E004DRYR" DRY0006A 352.36,4042.78 r90 top
IC6 "TPS73533DRBT" DRB0008A 1063.84,4284.85 r180 top
J1/J3 "SSQ-110-03-T-D" BoosterPack_40pin_J1J3 300,1955 r180 bottom locked
J2/J4 "SSQ-110-03-T-D" BoosterPack_40pin_J2J4 2000,1955 r180 bottom locked
J5 "PEC03SAAN" PEC03SAAN_Launchpad_3V3 250,1205 r90 top locked
J6 "90120-0122" CONN_90120-0122 250.8,903 r270 top
J7 "PEC03SAAN" PEC03SAAN_Launchpad_5V0 2050,1205 r90 top locked
J8 "90120-0122" CONN_90120-0122 275.18,2694.45 r270 top
J9 "90120-0122" CONN_90120-0122 573.53,429.62 r270 top
J10 "90120-0122" CONN_90120-0122 2086.38,2694.45 r270 top
J11 "90120-0122" CONN_90120-0122 250,429.62 r270 top
J12 "90120-0122" CONN_90120-0122 357.84,429.62 r270 top
J13 "90120-0122" CONN_90120-0122 465.68,429.62 r270 top
J14 "PEC03SAAN" CONN_PEC03SAAN 1503.61,1208.99 r270 top
J15 "PEC03SAAN" CONN_PEC03SAAN 1613.12,1208.99 r270 top
J16 "693071010811" FP-693071010811_CONN_SMT_MEMORY-MFG 1400,322 r0 top locked
J17 "90120-0122" CONN_90120-0122 472.69,118.18 r90 top
J18 "90120-0122" CONN_90120-0122 364.85,118.18 r90 top
J19 "90120-0122" CONN_90120-0122 257.01,118.18 r90 top
J20 "PEC04DAAN" CONN_PEC04DAAN 830.54,429.62 r180 top locked
J21 "PEC05DAAN" CONN_PEC05DAAN 780.54,118.18 r180 top locked
J22 "90120-0122" CONN_90120-0122 1900,935.77 r270 top
J23 "90120-0122" CONN_90120-0122 1908.32,69.43 r0 top
J24 "PEC03SAAN" CONN_PEC03SAAN 2141.16,253.58 r180 top
J25 "PEC03SAAN" CONN_PEC03SAAN 2141.16,363.09 r180 top
J101 "PEC10DAAN" SULLINS_PEC10DAAN 891.04,2890 r270 top locked
J102 "FTSH-105-01-L-DV-K" Samtec_FTSH-105-01-x-DV-K 1800,3055 r90 top
J103 "FTSH-105-01-L-DV-K" Samtec_FTSH-105-01-x-DV-K 1800,2723 r90 top
J104 "MUP-U20405" FP-MUP-U20405_USB_CONN-MFG 393.7,4317 r180 top locked
J105 "MUP-U20405" FP-MUP-U20405_USB_CONN-MFG 2167,679 r90 top locked
L1 "CBC2518T2R2M" CBC2518 2186.4,3748 r180 top value=2.2uH
LED1 "BR1111C-TR" 1111C_Red 560.57,704.89 r0 top value=Red
LED2 "19-337/R6GHBHC-A01/2T" 19-337_RGB 410,666 r180 top value=Rgb
LED3 "BR1111C-TR" 1111C_Red 2189.6,953.41 r0 top value=Red
LED101 "BR1111C-TR" 1111C_Red 107.12,3070.41 r180 top value=Red
LED102 "LTST-C190GKT" LED_LTST-C190 106,2989 r180 top value=Green
LOGO1 "CE Mark" CE_Mark_5mm 1162.08,1113 r180 bottom
Logo2 "Texas Instruments" TI_Horizontal_Overlay_Small 1296.33,3779.83 r90 top
Logo3 "Texas Instruments" TI_Horizontal_Overlay_Medium 1166,2546 r180 bottom
Logo4 "ESD Susceptible" ESD_Overlay_Large 1150,1885.69 r180 bottom
Logo5 "FCC disclaimer" FCC_disclaimer 3226,2019 r0 bottom
Logo6 "WEEE logo" WEEE_Minimum 840.07,1120.77 r180 bottom
MH1 "MTG_NoPads" NPTH125mil 95,4355 r0 top locked
MH2 "MTG_NoPads" NPTH125mil 2205,4355 r0 top locked
MH3 "MTG_NoPads" NPTH125mil 95,95 r0 top locked
MH4 "MTG_NoPads" NPTH125mil 2205,95 r0 top locked
MSP1 "MSPM0G5187SPMR" PM0064A-MFG 1150,2005 r0 top locked
R1 "CRCW040247K0JNED" 0402 182.65,2690.69 r90 top value=47k
R2 "CRCW040247K0JNED" 0402 1500.28,1583.28 r0 top value=47k
R3 "RC0603JR-070RL" 0603 884.91,1615.08 r90 top value=0
R4 "CRCW0402470RJNED" 0402 571.33,621.12 r0 top value=470
R5 "CRCW0402220RJNED" 0402 122.5,665.69 r90 top value=220
R6 "CRCW0402330RJNED" 0402 199.17,666 r90 top value=330
R7 "CRCW0402330RJNED" 0402 270,665.69 r90 top value=330
R8 "ERA-2AEB104X" FP-ERA-2AEB104X_0402-MFG 1645.62,1853.76 r180 top
R9 "RC0402JR-070RL" 0402 1668.68,1622.89 r90 top value=0
R10 "RC0402JR-070RL" 0402 1694.83,2011.17 r270 top value=0
R11 "RC0402JR-070RL" 0402 1694.83,2120.31 r90 top value=0
R12 "RC0603JR-074K7L" 0603 1558.49,1004.64 r0 top value=4.7k
R13 "CRCW0402270RJNED" 0402 1349.18,1309.81 r270 top value=270
R14 "RC0402JR-070RL" 0402 1682.61,2236.19 r270 top value=0
R15 "RC0603JR-074K7L" 0603 1803.71,1118.75 r0 top value=4.7k
R16 "RC0603JR-0710KL" 0603 1535.49,1483.28 r0 top value=2.2k
R17 "RC0402JR-070RL" 0402 1537.36,2408.02 r180 top value=0
R18 "CRCW0402270RJNED" 0402 1843.19,1211.62 r270 top value=270
R19 "RC0603JR-0710KL" 0603 1803.71,1307.91 r0 top value=2.2k
R20 "RC0402JR-070RL" 0402 712.75,1603.1 r90 top value=0
R21 "RC0402JR-070RL" 0402 906.5,1506.26 r0 top value=0
R22 "RC0402JR-070RL" 0402 646.74,1603.1 r90 top value=0
R23 "RC0603JR-070RL" 0603 1317.59,790.91 r90 top value=0
R24 "CRCW04024K70JNED" 0402 1440.68,2575.98 r90 top value=4.7k
R25 "CRCW04024K70JNED" 0402 1488.69,2575.98 r90 top value=4.7k
R26 "RC0603JR-0747KL" 0603 1609.1,804.58 r180 top value=47k
R27 "RC0603JR-074K7L" 0603 1609.1,737.57 r0 top value=4.7k
R28 "RC0603FR-0722RL" 0603 721.22,2211.25 r90 top value=22.0
R29 "RC0603JR-070RL" 0603 1162.81,2542.28 r0 top value=0
R30 "RC0603FR-0722RL" 0603 721.22,2084.27 r90 top value=22.0
R31 "RC0603JR-070RL" 0603 753.88,2542.28 r0 top value=0
R32 "RC0603FR-0722RL" 0603 721.22,1957.3 r90 top value=22.0
R33 "RC0603JR-070RL" 0603 890.19,2542.28 r0 top value=0
R34 "RC0603FR-0722RL" 0603 721.22,1830.32 r90 top value=22.0
R35 "RC0603JR-070RL" 0603 1026.5,2542.28 r180 top value=0
R36 "RC0603JR-070RL" 0603 1299.12,2542.34 r0 top value=0
R37 "RC0402JR-070RL" 0402 919.61,878.69 r270 top value=0
R38 "RC0603JR-070RL" 0603 412.97,921.84 r90 top value=0
R39 "RC0402JR-070RL" 0402 869.68,878.69 r270 top value=0
R40 "CRCW040247K0JNED" 0402 823.9,1235.28 r270 top value=47k
R41 "RC0402JR-070RL" 0402 819.76,878.69 r270 top value=0
R42 "CRCW040247K0JNED" 0402 1136.68,1062.36 r180 top value=47k
R43 "CRCW040247K0JNED" 0402 1136.47,966.34 r180 top value=47k
R44 "CRCW040247K0JNED" 0402 1136.47,1014.35 r180 top value=47k
R45 "RC0402FR-07330KL" 0402 1797.79,507.52 r270 top value=330k
R46 "RC0402FR-07220KL" 0402 1749.78,506.96 r270 top value=220k
R47 "RK73H1ETTP5602F" 0402 1905.04,199.64 r180 top value=56.0k
R48 "RK73H1ETTP5602F" 0402 1905.04,345.98 r180 top value=56.0k
R49 "CRCW04025K11FKED" 0402 1905.04,419.16 r0 top value=5.11k
R50 "CRCW04025K11FKED" 0402 1905.04,272.81 r0 top value=5.11k
R51 "ERJ-2GEJ102X" 0402 2052.37,955.6 r0 top value=1.0k
R52 "CRCW04021K00JNED" 0402 1075.66,3881 r0 top value=1.0k
R53 "CRCW04021K00JNED" 0402 1075.66,3829 r0 top value=1.0k
R54 "CRCW04021K00JNED" 0402 1075.66,3777 r0 top value=1.0k
R55 "CRCW04021K00JNED" 0402 1075.66,3725 r0 top value=1.0k
R56 "CRCW0402100RJNED" 0402 231,3975 r0 top value=100
R57 "CRCW0402470RJNED" 0402 239,3070 r0 top value=470
R58 "CRCW0402470RJNED" 0402 239,2989 r0 top value=470
R59 "CRCW040210K0JNED" 0402 774,4004 r90 top value=10k
R60 "CRCW04024K87FKED" 0402 1075.66,3673 r180 top value=4.87k
R61 "CRCW0402100RJNED" 0402 718.87,4004 r270 top value=100
R62 "CRCW04021K00JNED" 0402 580.4,3144.63 r270 top value=1.0k
R63 "CRCW040251R0JNED" 0402 1075.66,3985 r0 top value=51
R64 "RC0402FR-07220KL" 0402 1717,3655 r270 top value=220k
R65 "RC0402FR-07220KL" 0402 1717,3774.62 r270 top value=220k
R66 "ERJ-2RKF3301X" 0402 1907,3739 r0 top value=3.30k
R67 "CRCW04022K20FKED" 0402 1906.38,3849.2 r0 top value=2.20k
R68 "CRCW04026K81FKED" 0402 1906.38,3794 r0 top value=6.81k
R69 "CRCW04024K70JNED" 0402 1613,3656 r270 top value=4.7k
R70 "CRCW04024K70JNED" 0402 1551,3655.35 r270 top value=4.7k
R71 "RC0402FR-07220KL" 0402 1452,3581 r0 top value=220k
R72 "RC0402FR-07220KL" 0402 1452,3634 r0 top value=220k
R73 "RC0402FR-0747KL" 0402 1452,3526 r180 top value=47.0k
R74 "RC0402FR-0747KL" 0402 1452,3418 r0 top value=47.0k
R75 "RC0402FR-07820RL" 0402 1907,4046 r180 top value=820
R76 "CRCW0402470RJNED" 0402 2189,3981 r0 top value=470
R77 "RC0402FR-0747KL" 0402 1908.38,3578 r0 top value=47.0k
R78 "RC0402FR-07220KL" 0402 1908,3469 r0 top value=220k
R79 "RC0402FR-07220KL" 0402 231.62,3309 r180 top value=220k
R80 "RC0603JR-070RL" 0603 1907,3910.41 r0 top value=0
R81 "RC0402FR-07220KL" 0402 1907.62,3523 r180 top value=220k
R82 "RC0402FR-07220KL" 0402 231,3362 r0 top value=220k
R83 "ERJ-2RKF3301X" 0402 1083.93,3463.63 r0 top value=3.30k
R84 "RC0603JR-070RL" 0603 718.61,4319.83 r0 top value=0
R85 "RC0402FR-07330KL" 0402 231,3202 r0 top value=330k
R86 "CRCW04025K11FKED" 0402 705.59,4176.84 r180 top value=5.11k
R87 "RC0402FR-07220KL" 0402 231,3255 r0 top value=220k
R88 "CRCW04025K11FKED" 0402 705.59,4224.85 r180 top value=5.11k
R89 "CRCW040210K0JNED" 0402 142,3925.76 r90 top value=10k
R90 "CRCW040210K0JNED" 0402 142,3812.38 r90 top value=10k
R91 "RC0603JR-070RL" 0603 1720,750.75 r0 bottom value=0
R92 "RC0603JR-070RL" 0603 1720,669.51 r0 bottom value=0
S1 "1188E-1K2-V-TR" SW_1188E 73,2696 r0 top
S2 "1188E-1K2-V-TR" SW_1188E 2227,2696 r180 top
S3 "1188E-1K2-V-TR" SW_1188E 1842.84,4377 r270 top locked
SH-J1 "SNT-100-BK-G" SNT-100-BK-G 440.26,2889.81 r90 top value="J101: 1-2"
SH-J2 "SNT-100-BK-G" SNT-100-BK-G 540.37,2889.81 r90 top value="J101: 3-4"
SH-J3 "SNT-100-BK-G" SNT-100-BK-G 640.48,2889.81 r90 top value="J101: 5-6"
SH-J4 "SNT-100-BK-G" SNT-100-BK-G 740.59,2889.81 r90 top value="J101: 7-8"
SH-J5 "SNT-100-BK-G" SNT-100-BK-G 840.71,2889.81 r90 top value="J101: 9-10"
SH-J6 "SNT-100-BK-G" SNT-100-BK-G 940.82,2889.81 r90 top value="J101: 11-12"
SH-J7 "SNT-100-BK-G" SNT-100-BK-G 1040.93,2889.81 r90 top value="J101: 12-13"
SH-J8 "SNT-100-BK-G" SNT-100-BK-G 1141.04,2889.81 r90 top value="J101: 15-16"
SH-J9 "SNT-100-BK-G" SNT-100-BK-G 1241.15,2889.81 r90 top value="J101: 17-18"
SH-J10 "SNT-100-BK-G" SNT-100-BK-G 1341.27,2889.81 r90 top value="J101: 19-20"
SH-J11 "SNT-100-BK-G" SNT-100-BK-G 275.18,2690.97 r90 top value="J8: 1-2"
SH-J12 "SNT-100-BK-G" SNT-100-BK-G 573.53,429.62 r90 top value="J9: 1-2"
SH-J13 "SNT-100-BK-G" SNT-100-BK-G 2091.49,2694.45 r90 top value="J10: 1-2"
SH-J14 "SNT-100-BK-G" SNT-100-BK-G 250,429.62 r90 top value="J11: 1-2"
SH-J15 "SNT-100-BK-G" SNT-100-BK-G 357.84,429.62 r90 top value="J12: 1-2"
SH-J16 "SNT-100-BK-G" SNT-100-BK-G 465.68,429.62 r90 top value="J13: 1-2"
SH-J17 "SNT-100-BK-G" SNT-100-BK-G 1503.61,1258.99 r90 top value="J14: 2"
SH-J18 "SNT-100-BK-G" SNT-100-BK-G 1613.12,1258.99 r90 top value="J15: 2"
SH-J19 "SNT-100-BK-G" SNT-100-BK-G 1850,885.77 r0 top value="J23: 1-2"
SH-J20 "SNT-100-BK-G" SNT-100-BK-G 1808.32,69.43 r0 top value="J24: 1-2"
SH-J21 "SNT-100-BK-G" SNT-100-BK-G 2191.16,253.58 r0 top value="J25: 1-2"
SH-J22 "SNT-100-BK-G" SNT-100-BK-G 2191.16,363.09 r0 top value="J26: 1-2"
SH-J23 "SNT-100-BK-G" SNT-100-BK-G 201.22,852.45 r0 top value="J6: 1-2"
T1 "DMG1013UW-7" SOT-323 2191.4,3878.41 r0 top value=-20V
T2 "BC850CW,115" SOT-323 2034,3904 r0 top value="45 V"
TP1 "5001" Keystone5001 1601,3501 r90 top
TP2 "5001" Keystone5001 1601,3301 r90 top
TP3 "5001" Keystone5001 1601,3401 r90 top
TP4 "5001" Keystone5001 50,4090 r90 top
TP5 "5001" Keystone5001 50,3990 r90 top
TP6 "5001" Keystone5001 50,3890 r90 top
TP7 "5001" Keystone5001 50,3790 r90 top
TP8 "5001" Keystone5001 50,3690 r90 top
TP9 "5001" Keystone5001 50,3590 r90 top
TP10 "5001" Keystone5001 50,3490 r90 top
U1 "PCM1809IRTER" RTE0020A-MFG 915.32,1051.54 r0 top
U2 "ICS-40720" LGA_CAV-4 462.53,1127.17 r180 bottom
U3 "TPD6E004RSER" RSE0008A 1517.93,2768.49 r180 top
U4 "TPD4E05U06DQAR" DQA0010A 1930.91,740.03 r180 top
XDS1 "MSP432E401YTPDTR" PDT0128A 648,3583 r90 top locked
XDS2 "MSP430G2452IRSA16R" RSA0016B 1557,3858 r0 top
Y1 "X1A0001410014" Epson_FC-135 1530,2064.4 r270 top
Y2 "X1E0000210179" FP-X1E0000210179_TSX-3225-MFG 1546,2254.05 r270 top
Y3 "NX3225GA-16.000M-STD-CRG-1" NDK_NX3225GA 555,3998 r90 top
ZZ2 "These assemblies must be clean and free from flux and all contaminants. Use of no clean flux is not acceptable." AssemblyNote 145,5395 r0 top
ZZ3 "These assemblies must comply with workmanship standards IPC-A-610 Class 2, unless otherwise specified." AssemblyNote 140,5505 r0 top
ZZ4 "Place a click-in Standoff (MAE-10, KangYang)  in hole MH1/MH2" AssemblyNote 135,5600 r0 top

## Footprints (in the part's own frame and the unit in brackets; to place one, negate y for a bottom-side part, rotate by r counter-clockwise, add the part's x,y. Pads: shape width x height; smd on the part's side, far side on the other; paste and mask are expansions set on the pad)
19-337_RGB [mm] "SMD, 6-Leads, Body 1.6x1.6mm"
  rect 0.55x0.4 smd: 1(-0.675,0.725) 3(-0.675,-0.725) 4(0.675,0.725) 6(0.675,-0.725)
  rect 0.7x0.5 smd: 2(-0.75,0) 5(0.75,0)
  silkscreen extent -1.2,0.6 -1.2,0.9, body extent -0.85,-0.85 0.85,0.85, height 0.35
0402 [mm] "0402 from SM-752 data"
  rect 0.8x0.6 smd: 1(-0.6,0) 2(0.6,0)
  silkscreen extent -1.22,-0.52 1.22,0.52, body extent -0.55,-0.3 0.55,0.3, height 0.6
0603 [mm] "0603 from SM-752 data"
  rect 1x0.95 smd: 1(-0.8,0) 2(0.8,0)
  silkscreen extent -1.52,-0.69 1.52,0.69, body extent -0.87,-0.47 0.87,0.47, height 1
1111C_Red [mm] "SMD, 2-Leads, Body 1.6x0.8mm"
  rect 0.8x0.8 smd: 1(-0.8,0) 2(0.8,0)
  silkscreen extent -1,-0.7 1.7,0.7, body extent -0.85,-0.45 0.85,0.45, height 0.8
3216-18 [mm] "Based on AVX recommendation in http://www.avx.com/download/software/literature/AVX-Footprint-Library.pdf"
  rrect7% 1.4x1.8 smd: 1(-1.3,0) 2(1.3,0)
  silkscreen extent -1.9,-1.12 0.8,1.12, body extent -1.7,-0.9 1.7,0.9, height 1.82
AssemblyNote [mil] "Assembly Note"
BoosterPack_40pin_J1J3 [mm] "Receptacle, 2.54mm, 10x2, TH"
  rrect6% 1.55x1.55 hole 1.02: 1(1.27,11.43)
  round 1.55 hole 1.02: 2(1.27,8.89) 3(1.27,6.35) 4(1.27,3.81) 5(1.27,1.27) 6(1.27,-1.27) 7(1.27,-3.81) 8(1.27,-6.35) 9(1.27,-8.89) 10(1.27,-11.43) 21(-1.27,11.43) 22(-1.27,8.89) 23(-1.27,6.35) 24(-1.27,3.81) 25(-1.27,1.27) 26(-1.27,-1.27) 27(-1.27,-3.81) 28(-1.27,-6.35) 29(-1.27,-8.89) 30(-1.27,-11.43)
  silkscreen extent -7.62,-12.95 7.62,12.95, body extent -2.48,-12.95 2.48,12.95, height 8.51
BoosterPack_40pin_J2J4 [mm] "Receptacle, 2.54mm, 10x2, TH"
  round 1.55 hole 1.02: 11(-1.27,-11.43) 12(-1.27,-8.89) 13(-1.27,-6.35) 14(-1.27,-3.81) 15(-1.27,-1.27) 16(-1.27,1.27) 17(-1.27,3.81) 18(-1.27,6.35) 19(-1.27,8.89) 20(-1.27,11.43) 31(1.27,-11.43) 32(1.27,-8.89) 33(1.27,-6.35) 34(1.27,-3.81) 35(1.27,-1.27) 36(1.27,1.27) 37(1.27,3.81) 38(1.27,6.35) 39(1.27,8.89) 40(1.27,11.43)
  silkscreen extent -7.62,-12.95 2.48,12.95, body extent -2.48,-12.95 2.48,12.95, height 8.51
CBC2518 [mm] "Taiyo Yuden"
  rect 0.6x2 smd: 1(-1.05,0) 2(1.05,0)
  silkscreen extent -0.45,-1.1 0.45,1.1, body extent -1.35,-1 1.35,1, height 2
CE_Mark_5mm [mil] "Minimum text height for CE Mark"
  silkscreen extent -138,-98 138,98
CONN_90120-0122 [mm] "Molex"
  rect 1.65x1.65 hole 1.016 mask+0: 1(-1.27,0)
  round 1.65 hole 1.016 mask+0: 2(1.27,0)
  silkscreen extent -3.56,-1.27 2.54,1.27, body extent -2.54,-1.27 2.54,1.27, height 9.29
CONN_PEC03SAAN [mm] "SULLINS"
  rect 1.5x1.5 hole 1.016: 1(-2.54,0)
  round 1.5 hole 1.016: 2(0,0) 3(2.54,0)
  silkscreen extent -4.72,-1.27 3.81,1.27, body extent -3.84,-1.3 3.84,1.3, height 8.38
CONN_PEC04DAAN [mm] "SULLINS"
  rect 1.65x1.65 hole 1.016 mask+0: 1(-3.81,-1.27)
  round 1.65 hole 1.016 mask+0: 2(-3.81,1.27) 3(-1.27,-1.27) 4(-1.27,1.27) 5(1.27,-1.27) 6(1.27,1.27) 7(3.81,-1.27) 8(3.81,1.27)
  silkscreen extent -6.18,-2.6 5.08,2.54, body extent -5.08,-2.54 5.08,2.54, height 8.38
CONN_PEC05DAAN [mm] "SULLINS"
  rect 1.65x1.65 hole 1.016 mask+0: 1(-5.08,-1.27)
  round 1.65 hole 1.016 mask+0: 2(-5.08,1.27) 3(-2.54,-1.27) 4(-2.54,1.27) 5(0,-1.27) 6(0,1.27) 7(2.54,-1.27) 8(2.54,1.27) 9(5.08,-1.27) 10(5.08,1.27)
  silkscreen extent -7.45,-2.6 6.35,2.54, body extent -6.35,-2.54 6.35,2.54, height 8.38
DBV0005A_N [mm] "SOT23, 5-Leads, Body 2.9x1.6mm, Pitch 0.95mm, Lead Span 2.8mm, IPC Medium Density"
  rrect17% 1x0.6 smd: 1(-1.375,0.95) 2(-1.375,0) 3(-1.375,-0.95) 4(1.375,-0.95) 5(1.375,0.95)
  silkscreen extent -0.25,-1.55 0.25,1.55, body extent -1.42,-1.46 1.42,1.46, height 1.09
DCK0005A_N [mm] "SOT353, 5-Leads, Body 2x1.3mm, Pitch 0.65mm, Lead Span 2.1mm, IPC Medium Density"
  rrect25% 0.85x0.4 smd: 1(-1.125,0.65) 2(-1.125,0) 3(-1.125,-0.65) 4(1.125,-0.65) 5(1.125,0.65)
  silkscreen extent -1.48,-1.02 0.55,1.1, body extent -1.14,-1 1.14,1, height 0.95
DQA0010A [mm] "SON, 10-Leads, Body 1x2.5mm, Pitch 0.5mm, TI Recommended"
  rrect50% 0.565x0.2 smd: 1(-0.417,1) 2(-0.417,0.5) 4(-0.417,-0.5) 5(-0.417,-1) 6(0.417,-1) 7(0.417,-0.5) 9(0.417,0.5) 10(0.417,1)
  rrect28% 0.565x0.36 on Top Paste: 3(-0.417,0) 8(0.417,0)
  rrect25% 0.565x0.4 smd paste-0.2: 3(-0.417,0) 8(0.417,0)
  silkscreen extent -0.67,-1.45 0.55,1.45, body extent -0.55,-1.3 0.55,1.3, height 0.56
DRB0008A [mm] "VSON-8"
  rrect32% 0.6x0.31 smd: 1(-1.4,0.975) 2(-1.4,0.325) 3(-1.4,-0.325) 4(-1.4,-0.975) 5(1.4,-0.975) 6(1.4,-0.325) 7(1.4,0.325) 8(1.4,0.975)
  rrect7% 1.5x1.75 smd paste-0.75: 9(0,0)
  Top Layer region: -0.7,-0.875 -0.49,-0.875 -0.471,-0.879 -0.455,-0.89 -0.444,-0.906 -0.44,-0.925 -0.44,-0.925 -0.44,-1.65 -0.436,-1.669 -0.425,-1.685 -0.409,-1.696 -0.39,-1.7 -0.39,-1.7 -0.26,-1.7 -0.241,-1.696 -0.225,-1.685 -0.214,-1.669 -0.21,-1.65 -0.21,-1.65 -0.21,-0.925 -0.206,-0.906 -0.195,-0.89 -0.179,-0.879 -0.16,-0.875 -0.16,-0.875 0.16,-0.875 0.179,-0.879 0.195,-0.89 0.206,-0.906 0.21,-0.925 0.21,-0.925 0.21,-1.65 0.21,-1.65 0.214,-1.669 0.225,-1.685 0.241,-1.696 0.26,-1.7 0.26,-1.7 0.39,-1.7 0.409,-1.696 0.425,-1.685 0.436,-1.669 0.44,-1.65 0.44,-1.65 0.44,-0.925 0.444,-0.906 0.455,-0.89 0.471,-0.879 0.49,-0.875 0.49,-0.875 0.7,-0.875 0.719,-0.871 0.735,-0.86 0.746,-0.844 0.75,-0.825 0.75,-0.825 0.75,0.825 0.746,0.844 0.735,0.86 0.719,0.871 0.7,0.875 0.7,0.875 0.49,0.875 0.471,0.879 0.455,0.89 0.444,0.906 0.44,0.925 0.44,0.925 0.44,1.65 0.436,1.669 0.425,1.685 0.409,1.696 0.39,1.7 0.39,1.7 0.26,1.7 0.241,1.696 0.225,1.685 0.214,1.669 0.21,1.65 0.21,1.65 0.21,1.65 0.21,0.925 0.206,0.906 0.195,0.89 0.179,0.879 0.16,0.875 0.16,0.875 -0.16,0.875 -0.179,0.879 -0.195,0.89 -0.206,0.906 -0.21,0.925 -0.21,0.925 -0.21,1.65 -0.214,1.669 -0.225,1.685 -0.241,1.696 -0.26,1.7 -0.26,1.7 -0.39,1.7 -0.409,1.696 -0.425,1.685 -0.436,1.669 -0.44,1.65 -0.44,1.65 -0.44,0.925 -0.444,0.906 -0.455,0.89 -0.471,0.879 -0.49,0.875 -0.49,0.875 -0.7,0.875 -0.719,0.871 -0.735,0.86 -0.746,0.844 -0.75,0.825 -0.75,0.825 -0.75,-0.825 -0.746,-0.844 -0.735,-0.86 -0.719,-0.871 -0.7,-0.875
  silkscreen extent -1.73,-1.73 1.73,1.73, body extent -1.5,-1.5 1.5,1.5, height 0.77
DRY0006A [mm] "PSON, 6-Leads, Body 1x1.45mm, Pitch 0.5mm, TI Recommended"
  rect 0.35x0.2 smd: 1(-0.275,0.5)
  rect 0.3x0.2 smd: 2(-0.3,0) 3(-0.3,-0.5) 4(0.3,-0.5) 5(0.3,0) 6(0.3,0.5)
  silkscreen extent -0.5,-0.85 0.2,0.85, body extent -0.53,-0.75 0.53,0.75, height 0.61
Epson_FC-135 [mm] "SMD, 2-Leads, Body 3.2x1.5mm"
  rect 1x1.8 smd: 1(-1.25,0) 2(1.25,0)
  silkscreen extent -0.35,-0.8 0.35,0.8, body extent -1.65,-0.8 1.65,0.8, height 0.9
ESD_Overlay_Large [mil]
  silkscreen extent -254,-219 250,219
FCC_disclaimer [mil]
Fiducial10-30 [mm]
  round 1 smd mask+1: 1(0,0)
  Top Layer keep-out circle w1.678: c0,0 r0.75
FP-693071010811_CONN_SMT_MEMORY-MFG [mm]
  rrect13% 0.8x1.5 smd paste+0 mask+0: 1(1.94,-3.1) 2(0.84,-2.7) 3(-0.26,-3.1) 4(-1.36,-3.3) 5(-2.46,-3.1) 6(-3.56,-3.3) 7(-4.66,-3.1) 8(-5.76,-3.1)
  rrect7% 1.4x1.9 smd paste+0 mask+0: 9(-6.55,-5.95) 9(6.6,-6.95)
  rrect7% 1.8x1.4 smd paste+0 mask+0: 10(-4.95,7.2) 10(0.75,7.2)
  silkscreen extent -7.12,-8.65 7.12,7.7, body extent -7.35,-8 7.4,8, height 0.25
FP-ERA-2AEB104X_0402-MFG [mm]
  rrect21% 0.475x0.5 smd paste+0 mask+0: 1(-0.512,0) 2(0.512,0)
  silkscreen extent -0.5,-0.63 0.5,0.63, body extent -0.85,-0.4 0.85,0.4, height 0.25
FP-MUP-U20405_USB_CONN-MFG [mm]
  rrect100% 1.2x2 hole 1.4 slot 0.6 at 0 deg paste-1000 mask+0: 1(-4.32,3) 2(4.32,3)
  rrect100% 1.2x2.1 hole 1.5 slot 0.6 at 0 deg paste-1000 mask+0: 3(-4.32,-1.5) 4(4.32,-1.5)
  rrect40% 0.25x0.8 smd paste+0 mask+0: A1(-2.6,3.45) A4(-1.8,3.45) A5(-1.4,3.45) A6(-1,3.45) A7(-0.6,3.45) A8(-0.2,3.45) A9(2.2,3.45) A12(3,3.45) B1(2.6,3.45) B4(1.8,3.45) B5(1.4,3.45) B6(1,3.45) B7(0.6,3.45) B8(0.2,3.45) B9(-2.2,3.45) B12(-3,3.45)
  silkscreen extent -4.59,-0.08 4.59,4.55, body extent -5.02,-3.67 5.02,4.1, height 0.25
FP-X1E0000210179_TSX-3225-MFG [mm]
  rrect9% 1.4x1.15 smd paste+0 mask+0: 1(-1.1,-0.8) 2(1.1,-0.8) 3(1.1,0.8) 4(-1.1,0.8)
  silkscreen extent -1.22,-2.05 0,1.33, body extent -1.9,-1.48 1.9,1.48, height 0.25
Keystone5001 [mil] "For Keystone 500x miniature loop terminals"
  round 80 hole 40: 1(0,0)
  silkscreen extent -52,-52 52,52, body extent -49,-49 49,49, height 182
KY_MAE-10 [mil] "Spacer Nylon Support"
  body extent -125,-108 125,108, height 394
LED_LTST-C190 [mm] "Lite-On"
  rect 0.8x0.8 smd: 1(-0.75,0) 2(0.75,0)
  silkscreen extent -1.1,-0.8 1.8,0.8, body extent -0.85,-0.45 0.85,0.45, height 0.9
LGA_CAV-4 [mm] "SMD, 4-Leads, Body 4x3mm"
  rrect19% 0.73x0.53 smd paste-0.05: 1(-1.405,0.88) 2(-1.405,0) 3(-1.405,-0.88)
  rrect100% 0.3x0.2 smd: 4(0.68,-0.92)
  Top Layer lines w0.3: 0.68,-0.92 ccw(c0.68,0) -0.24,0 ccw(c0.68,0) 0.68,-0.92
  silkscreen extent -2.1,-1.6 2.1,1.6, body extent -2.05,-1.55 2.05,1.55, height 1.3
NDK_NX3225GA [mm] "NDK"
  rect 1.2x1.4 smd: 1(-0.8,1.1) 2(-0.8,-1.1) 3(0.8,-1.1) 4(0.8,1.1)
  silkscreen extent -1.9,-0.1 1.4,2, body extent -1.3,-1.65 1.3,1.65, height 0.9
NPTH125mil [mil]
  round 120 hole 125 unplated mask+15: 1(0,0)
PDT0128A [mm] "Thin QFP, 128-Leads, Body 14x14mm, Pitch 0.4mm"
  oval 1.4x0.2 smd: 1(-7.7,6.2) 2(-7.7,5.8) 3(-7.7,5.4) 4(-7.7,5) 5(-7.7,4.6) 6(-7.7,4.2) 7(-7.7,3.8) 8(-7.7,3.4) 9(-7.7,3) 10(-7.7,2.6) 11(-7.7,2.2) 12(-7.7,1.8) 13(-7.7,1.4) 14(-7.7,1) 15(-7.7,0.6) 16(-7.7,0.2) 17(-7.7,-0.2) 18(-7.7,-0.6) 19(-7.7,-1) 20(-7.7,-1.4) 21(-7.7,-1.8) 22(-7.7,-2.2) 23(-7.7,-2.6) 24(-7.7,-3) 25(-7.7,-3.4) 26(-7.7,-3.8) 27(-7.7,-4.2) 28(-7.7,-4.6) 29(-7.7,-5) 30(-7.7,-5.4) 31(-7.7,-5.8) 32(-7.7,-6.2) 65(7.7,-6.2) 66(7.7,-5.8) 67(7.7,-5.4) 68(7.7,-5) 69(7.7,-4.6) 70(7.7,-4.2) 71(7.7,-3.8) 72(7.7,-3.4) 73(7.7,-3) 74(7.7,-2.6) 75(7.7,-2.2) 76(7.7,-1.8) 77(7.7,-1.4) 78(7.7,-1) 79(7.7,-0.6) 80(7.7,-0.2) 81(7.7,0.2) 82(7.7,0.6) 83(7.7,1) 84(7.7,1.4) 85(7.7,1.8) 86(7.7,2.2) 87(7.7,2.6) 88(7.7,3) 89(7.7,3.4) 90(7.7,3.8) 91(7.7,4.2) 92(7.7,4.6) 93(7.7,5) 94(7.7,5.4) 95(7.7,5.8) 96(7.7,6.2)
  oval 0.2x1.4 smd: 33(-6.2,-7.7) 34(-5.8,-7.7) 35(-5.4,-7.7) 36(-5,-7.7) 37(-4.6,-7.7) 38(-4.2,-7.7) 39(-3.8,-7.7) 40(-3.4,-7.7) 41(-3,-7.7) 42(-2.6,-7.7) 43(-2.2,-7.7) 44(-1.8,-7.7) 45(-1.4,-7.7) 46(-1,-7.7) 47(-0.6,-7.7) 48(-0.2,-7.7) 49(0.2,-7.7) 50(0.6,-7.7) 51(1,-7.7) 52(1.4,-7.7) 53(1.8,-7.7) 54(2.2,-7.7) 55(2.6,-7.7) 56(3,-7.7) 57(3.4,-7.7) 58(3.8,-7.7) 59(4.2,-7.7) 60(4.6,-7.7) 61(5,-7.7) 62(5.4,-7.7) 63(5.8,-7.7) 64(6.2,-7.7) 97(6.2,7.7) 98(5.8,7.7) 99(5.4,7.7) 100(5,7.7) 101(4.6,7.7) 102(4.2,7.7) 103(3.8,7.7) 104(3.4,7.7) 105(3,7.7) 106(2.6,7.7) 107(2.2,7.7) 108(1.8,7.7) 109(1.4,7.7) 110(1,7.7) 111(0.6,7.7) 112(0.2,7.7) 113(-0.2,7.7) 114(-0.6,7.7) 115(-1,7.7) 116(-1.4,7.7) 117(-1.8,7.7) 118(-2.2,7.7) 119(-2.6,7.7) 120(-3,7.7) 121(-3.4,7.7) 122(-3.8,7.7) 123(-4.2,7.7) 124(-4.6,7.7) 125(-5,7.7) 126(-5.4,7.7) 127(-5.8,7.7) 128(-6.2,7.7)
  silkscreen extent -7.7,-6.3 6.3,6.99, body extent -8,-8 8,8, height 1.07
PEC03SAAN_Launchpad_3V3 [mm] "SULLINS"
  rect 1.65x1.65 hole 1.016: 1(-2.54,0)
  round 1.65 hole 1.016: 2(0,0) 3(2.54,0)
  silkscreen extent -3.81,-1.27 3.81,6.3, body extent -3.84,-1.3 3.84,1.3, height 8.38
PEC03SAAN_Launchpad_5V0 [mm] "SULLINS"
  rect 1.65x1.65 hole 1.016: 1(-2.54,0)
  round 1.65 hole 1.016: 2(0,0) 3(2.54,0)
  silkscreen extent -3.81,-6.31 3.81,1.27, body extent -3.84,-1.3 3.84,1.3, height 8.38
PM0064A-MFG [mm] "Recommended Land Pattern"
  rrect33% 1.5x0.3 smd paste+0 mask+0: 1(-5.7,3.75) 2(-5.7,3.25) 3(-5.7,2.75) 4(-5.7,2.25) 5(-5.7,1.75) 6(-5.7,1.25) 7(-5.7,0.75) 8(-5.7,0.25) 9(-5.7,-0.25) 10(-5.7,-0.75) 11(-5.7,-1.25) 12(-5.7,-1.75) 13(-5.7,-2.25) 14(-5.7,-2.75) 15(-5.7,-3.25) 16(-5.7,-3.75) 33(5.7,-3.75) 34(5.7,-3.25) 35(5.7,-2.75) 36(5.7,-2.25) 37(5.7,-1.75) 38(5.7,-1.25) 39(5.7,-0.75) 40(5.7,-0.25) 41(5.7,0.25) 42(5.7,0.75) 43(5.7,1.25) 44(5.7,1.75) 45(5.7,2.25) 46(5.7,2.75) 47(5.7,3.25) 48(5.7,3.75)
  rrect33% 0.3x1.5 smd paste+0 mask+0: 17(-3.75,-5.7) 18(-3.25,-5.7) 19(-2.75,-5.7) 20(-2.25,-5.7) 21(-1.75,-5.7) 22(-1.25,-5.7) 23(-0.75,-5.7) 24(-0.25,-5.7) 25(0.25,-5.7) 26(0.75,-5.7) 27(1.25,-5.7) 28(1.75,-5.7) 29(2.25,-5.7) 30(2.75,-5.7) 31(3.25,-5.7) 32(3.75,-5.7) 49(3.75,5.7) 50(3.25,5.7) 51(2.75,5.7) 52(2.25,5.7) 53(1.75,5.7) 54(1.25,5.7) 55(0.75,5.7) 56(0.25,5.7) 57(-0.25,5.7) 58(-0.75,5.7) 59(-1.25,5.7) 60(-1.75,5.7) 61(-2.25,5.7) 62(-2.75,5.7) 63(-3.25,5.7) 64(-3.75,5.7)
  silkscreen extent -7.12,-5.1 5.1,5.1, body extent -6,-6 6,6, height 1.6
RSA0016B [mm] "QFN, 16-Leads, Body 4x4mm, Pitch 0.65mm, Thermal Pad 2.7x2.7mm, TI Recommended"
  oval 0.6x0.3 smd: 1(-1.9,0.975) 2(-1.9,0.325) 3(-1.9,-0.325) 4(-1.9,-0.975) 9(1.9,-0.975) 10(1.9,-0.325) 11(1.9,0.325) 12(1.9,0.975)
  oval 0.3x0.6 smd: 5(-0.975,-1.9) 6(-0.325,-1.9) 7(0.325,-1.9) 8(0.975,-1.9) 13(0.975,1.9) 14(0.325,1.9) 15(-0.325,1.9) 16(-0.975,1.9)
  rect 2.7x2.7 smd paste-1.35: 17(0,0)
  Top Layer keep-out region: -2,1.5 -1.5,1.5 -1.5,2 -2,2
  silkscreen extent -2.2,-2.2 2.2,2.2, body extent -2.05,-2.05 2.05,2.05, height 1.01
RSE0008A [mm] "QFN, 8-Leads, Body 1.5x1.5mm, Pitch 0.5mm, TI Recommended"
  rrect40% 0.55x0.25 smd: 1(-0.675,0.5) 3(-0.675,-0.5) 5(0.675,-0.5) 7(0.675,0.5)
  rrect50% 0.55x0.2 smd: 2(-0.675,0) 6(0.675,0)
  rrect33% 0.3x0.6 smd: 4(0,-0.65) 8(0,0.65)
  silkscreen extent -1.02,-0.92 0.77,0.93, body extent -0.75,-0.75 0.75,0.75, height 0.6
RTE0020A-MFG [mm]
  rrect40% 0.6x0.25 smd paste+0 mask+0: 1(-1.4,0.75) 2(-1.4,0.25) 3(-1.4,-0.25) 4(-1.4,-0.75) 11(1.4,-0.75) 12(1.4,-0.25) 13(1.4,0.25) 14(1.4,0.75)
  round 0.171 smd paste+0 mask+0: 5(-1.233,-1.233) 10(1.233,-1.233) 15(1.233,1.233) 20(-1.233,1.233)
  rrect40% 0.25x0.6 smd paste+0 mask+0: 6(-0.75,-1.4) 7(-0.25,-1.4) 8(0.25,-1.4) 9(0.75,-1.4) 16(0.75,1.4) 17(0.25,1.4) 18(-0.25,1.4) 19(-0.75,1.4)
  rrect7% 1.4x1.4 smd paste-1000 mask+0: 21(0,0)
  Top Layer region: 1.65,1.125 1.669,1.129 1.685,1.14 1.696,1.156 1.7,1.175 1.7,1.175 1.7,1.25 1.693,1.275 1.675,1.293 1.65,1.3 1.65,1.3 1.3,1.3 1.3,1.65 1.293,1.675 1.275,1.693 1.25,1.7 1.25,1.7 1.175,1.7 1.15,1.693 1.132,1.675 1.125,1.65 1.125,1.65 1.125,1.175 1.129,1.156 1.14,1.14 1.156,1.129 1.175,1.125 1.175,1.125
  Top Layer region: 1.65,-1.125 1.669,-1.129 1.685,-1.14 1.696,-1.156 1.7,-1.175 1.7,-1.175 1.7,-1.25 1.693,-1.275 1.675,-1.293 1.65,-1.3 1.65,-1.3 1.3,-1.3 1.3,-1.65 1.293,-1.675 1.275,-1.693 1.25,-1.7 1.25,-1.7 1.175,-1.7 1.15,-1.693 1.132,-1.675 1.125,-1.65 1.125,-1.65 1.125,-1.175 1.129,-1.156 1.14,-1.14 1.156,-1.129 1.175,-1.125 1.175,-1.125
  Top Layer region: -1.65,-1.125 -1.669,-1.129 -1.685,-1.14 -1.696,-1.156 -1.7,-1.175 -1.7,-1.175 -1.7,-1.25 -1.693,-1.275 -1.675,-1.293 -1.65,-1.3 -1.65,-1.3 -1.3,-1.3 -1.3,-1.65 -1.293,-1.675 -1.275,-1.693 -1.25,-1.7 -1.25,-1.7 -1.175,-1.7 -1.15,-1.693 -1.132,-1.675 -1.125,-1.65 -1.125,-1.65 -1.125,-1.175 -1.129,-1.156 -1.14,-1.14 -1.156,-1.129 -1.175,-1.125 -1.175,-1.125
  Top Layer region: -1.65,1.125 -1.669,1.129 -1.685,1.14 -1.696,1.156 -1.7,1.175 -1.7,1.175 -1.7,1.25 -1.693,1.275 -1.675,1.293 -1.65,1.3 -1.65,1.3 -1.3,1.3 -1.3,1.65 -1.293,1.675 -1.275,1.693 -1.25,1.7 -1.25,1.7 -1.175,1.7 -1.15,1.693 -1.132,1.675 -1.125,1.65 -1.125,1.65 -1.125,1.175 -1.129,1.156 -1.14,1.14 -1.156,1.129 -1.175,1.125 -1.175,1.125
  silkscreen extent -2.37,-1.9 1.9,1.9, body extent -1.8,-1.8 1.8,1.8, height 0.25
Samtec_FTSH-105-01-x-DV-K [mm] "Header(Shrouded), 1.27mm, 5x2, SMT"
  rect 2.79x0.74 smd: 1(-2.035,2.54) 2(2.035,2.54) 3(-2.035,1.27) 4(2.035,1.27) 5(-2.035,0) 6(2.035,0) 7(-2.035,-1.27) 8(2.035,-1.27) 9(-2.035,-2.54) 10(2.035,-2.54)
  silkscreen extent -3.73,-3.48 3.73,3.48, body extent -2.92,-3.18 2.92,3.17, height 6.13
SNT-100-BK-G [mil] "Samtec STEP model"
  round 1 on Mech3: 0(0,0)
  body extent -100,-50 100,50, height 344
SOT-323 [mm] "Diodes Inc recommended land pattern.  2016-02-24"
  rrect21% 0.6x0.47 smd: 1(-0.95,0.65) 2(-0.95,-0.65) 3(0.95,0)
  silkscreen extent -1.14,-1.22 0.77,1.22, body extent -1.13,-1.13 1.12,1.12, height 1.13
SULLINS_PEC10DAAN [mm] "SULLINS"
  rrect50% 1.55x1.55 hole 1.016: 1(-1.27,-11.43)
  round 1.55 hole 1.016: 2(1.27,-11.43) 3(-1.27,-8.89) 4(1.27,-8.89) 5(-1.27,-6.35) 6(1.27,-6.35) 7(-1.27,-3.81) 8(1.27,-3.81) 9(-1.27,-1.27) 10(1.27,-1.27) 11(-1.27,1.27) 12(1.27,1.27) 13(-1.27,3.81) 14(1.27,3.81) 15(-1.27,6.35) 16(1.27,6.35) 17(-1.27,8.89) 18(1.27,8.89) 19(-1.27,11.43) 20(1.27,11.43)
  silkscreen extent -2.9,-12.7 2.54,12.7, body extent -2.54,-12.7 2.54,12.7, height 8.38
SW_1188E [mm] "SMD, 4-Leads, Body 7.8x3.5mm"
  rrect10% 1x1.45 smd: 1(-1.1,3.375) 2(-1.1,-3.375)
  rrect11% 1.3x0.9 smd: 3(0.7,2.1) 4(0.7,-2.1)
  round 0 hole 0.9 unplated: ""(-0.35,-1.15) ""(-0.35,1.15)
  silkscreen extent -1.97,-2.28 0.95,2.28, body extent -2.55,-3.9 1.05,3.9, height 3.5
TI_Horizontal_Overlay_Medium [mil]
  silkscreen extent -750,-93 750,94
TI_Horizontal_Overlay_Small [mil]
  silkscreen extent -545,-68 545,67
WEEE_Minimum [mil] "WEEElie bin"
  silkscreen extent -95,-172 99,104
